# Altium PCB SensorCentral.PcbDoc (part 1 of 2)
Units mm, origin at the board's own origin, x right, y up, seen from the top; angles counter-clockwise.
Board outline 99.21 x 99.07 mm, 6 copper layers (Top Layer 1, GND1, Signal, GND2, GND3, Bottom Layer 1), stack 1.538 mm thick; 91 components, 67 nets, 452 pads, 462 vias.
Unrouted connection lines stored in the file: 278.
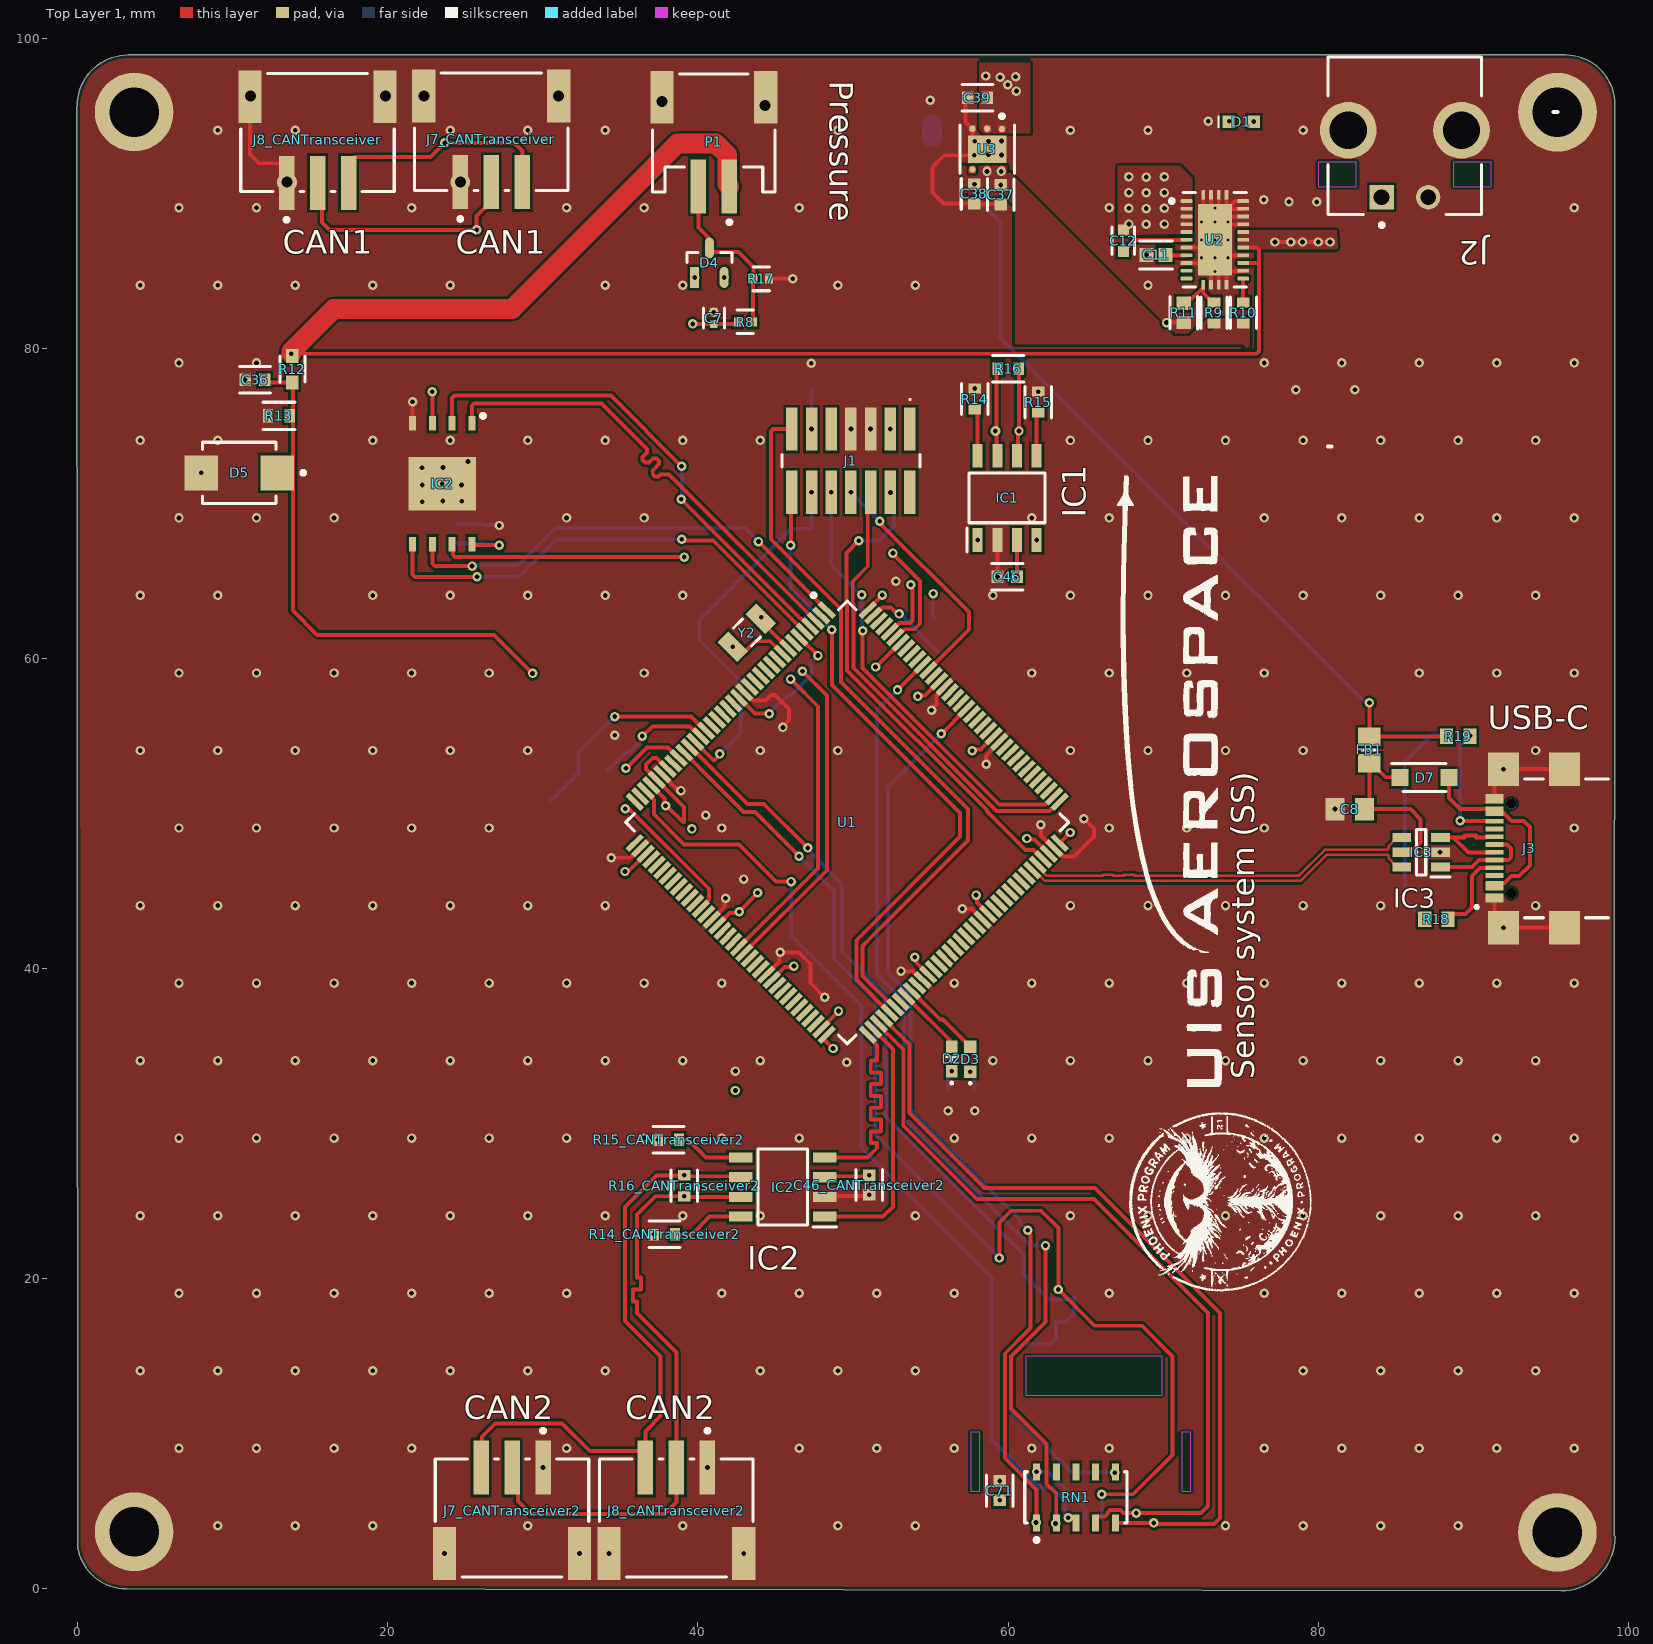
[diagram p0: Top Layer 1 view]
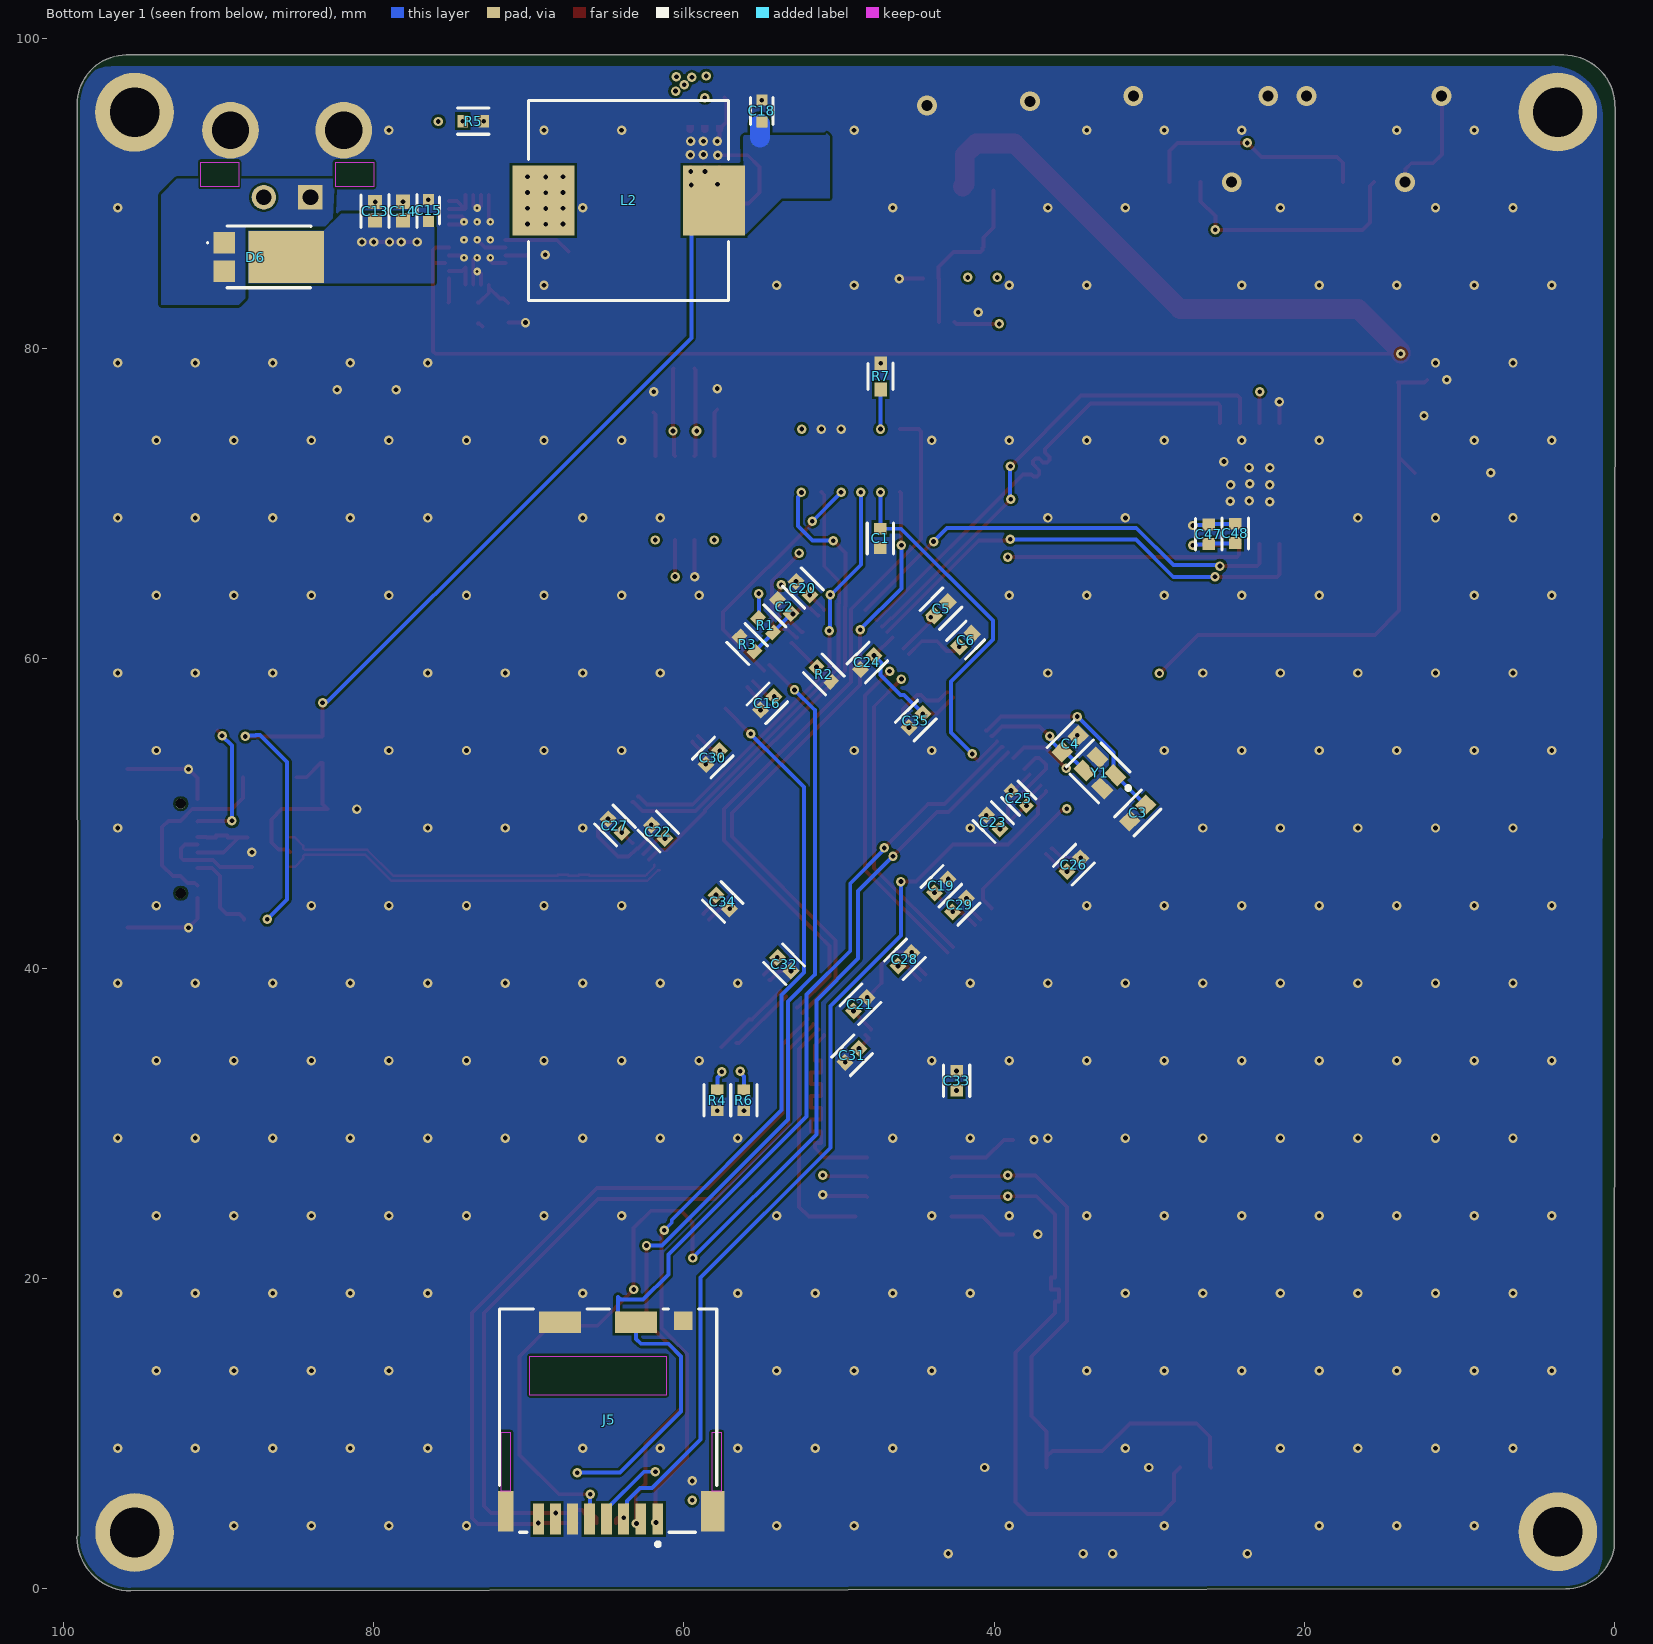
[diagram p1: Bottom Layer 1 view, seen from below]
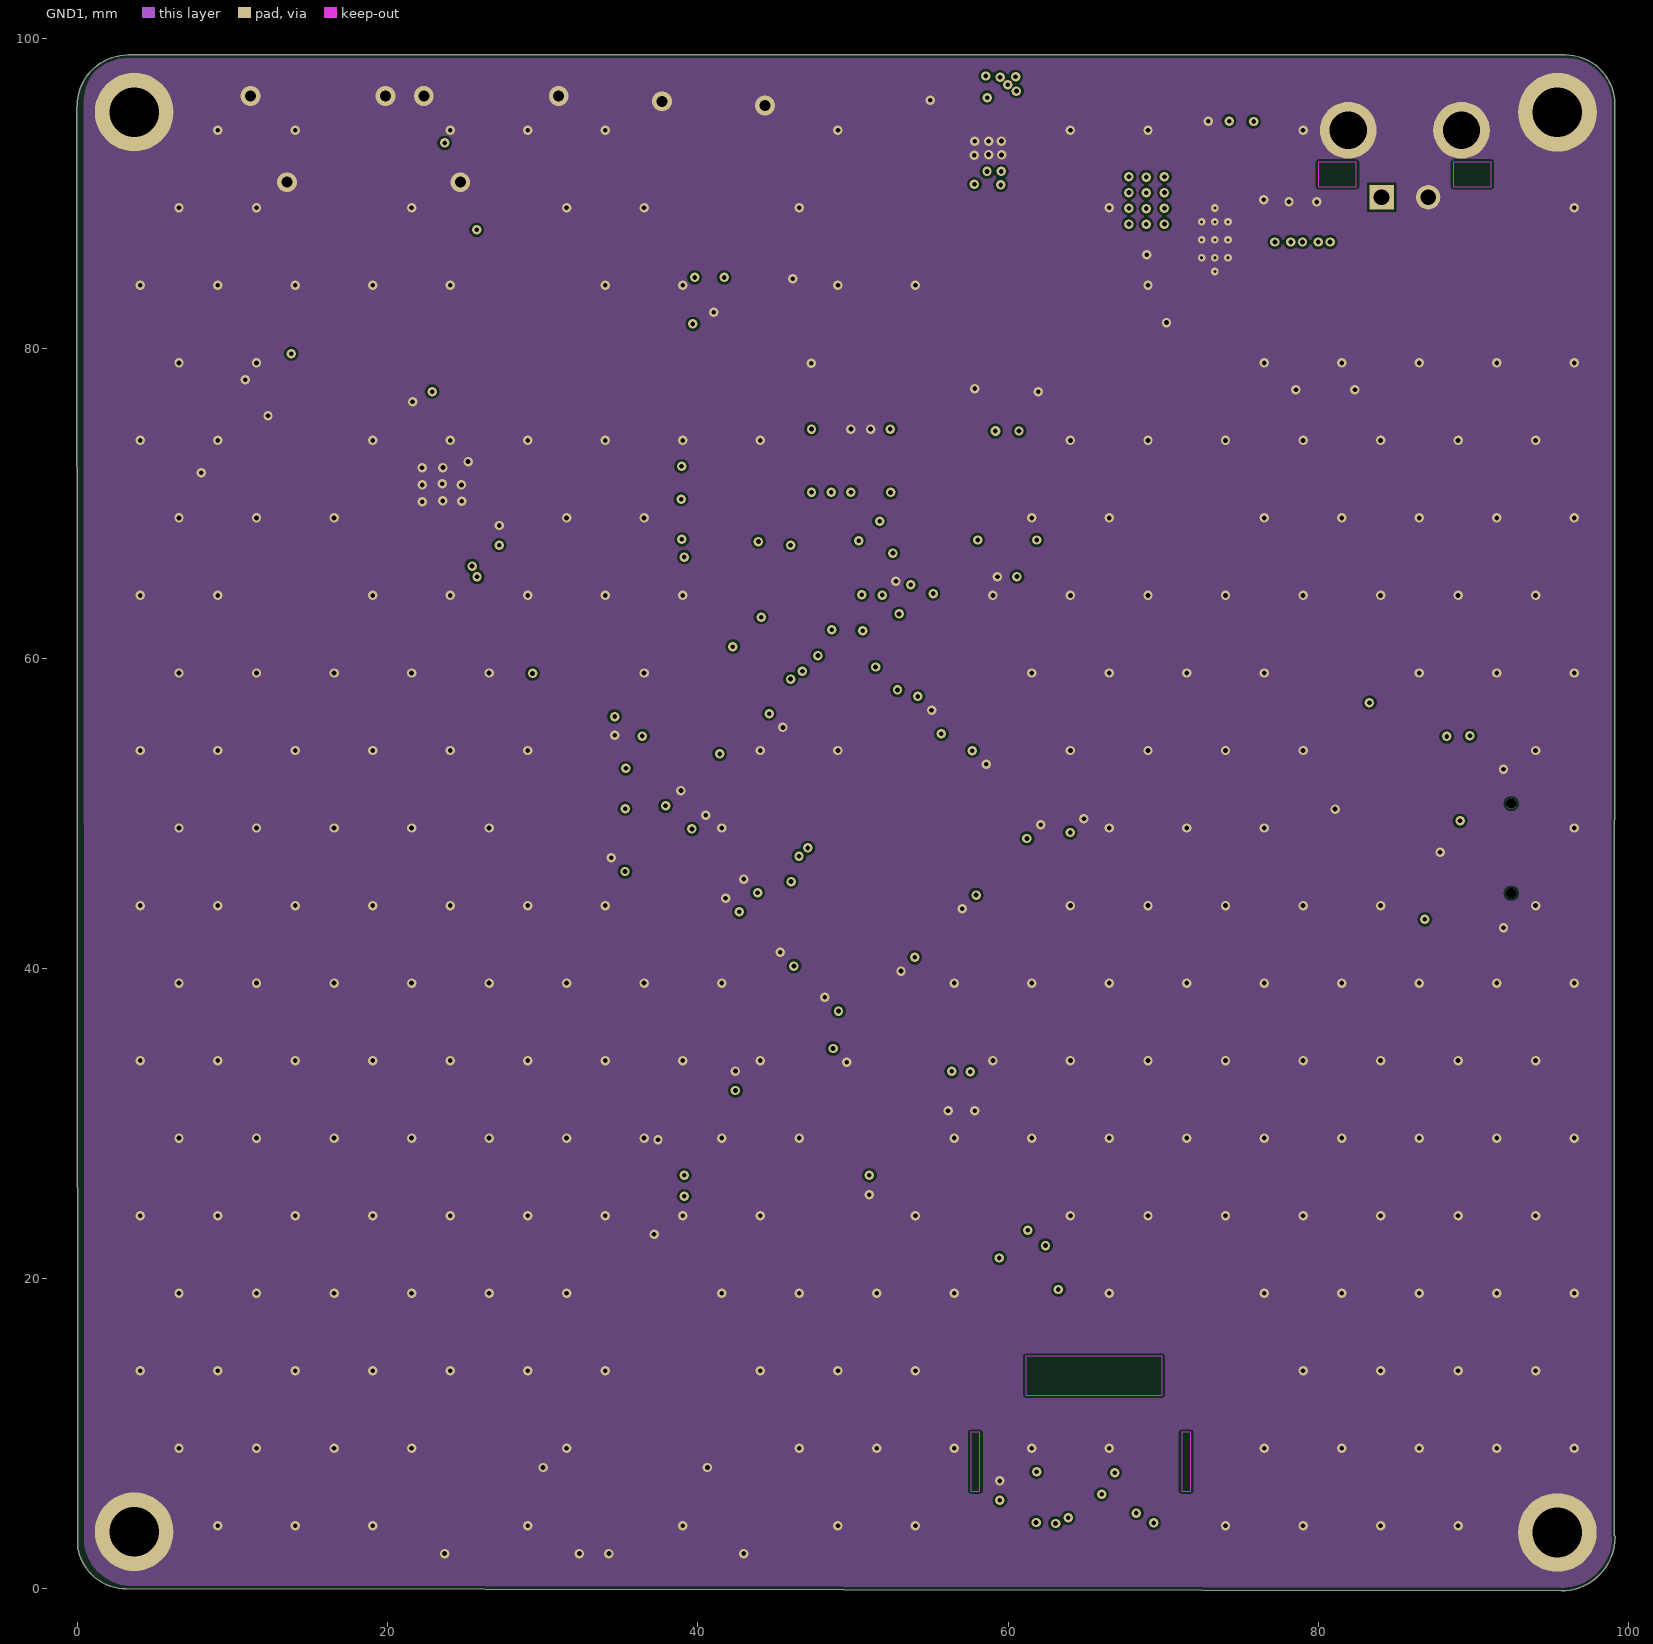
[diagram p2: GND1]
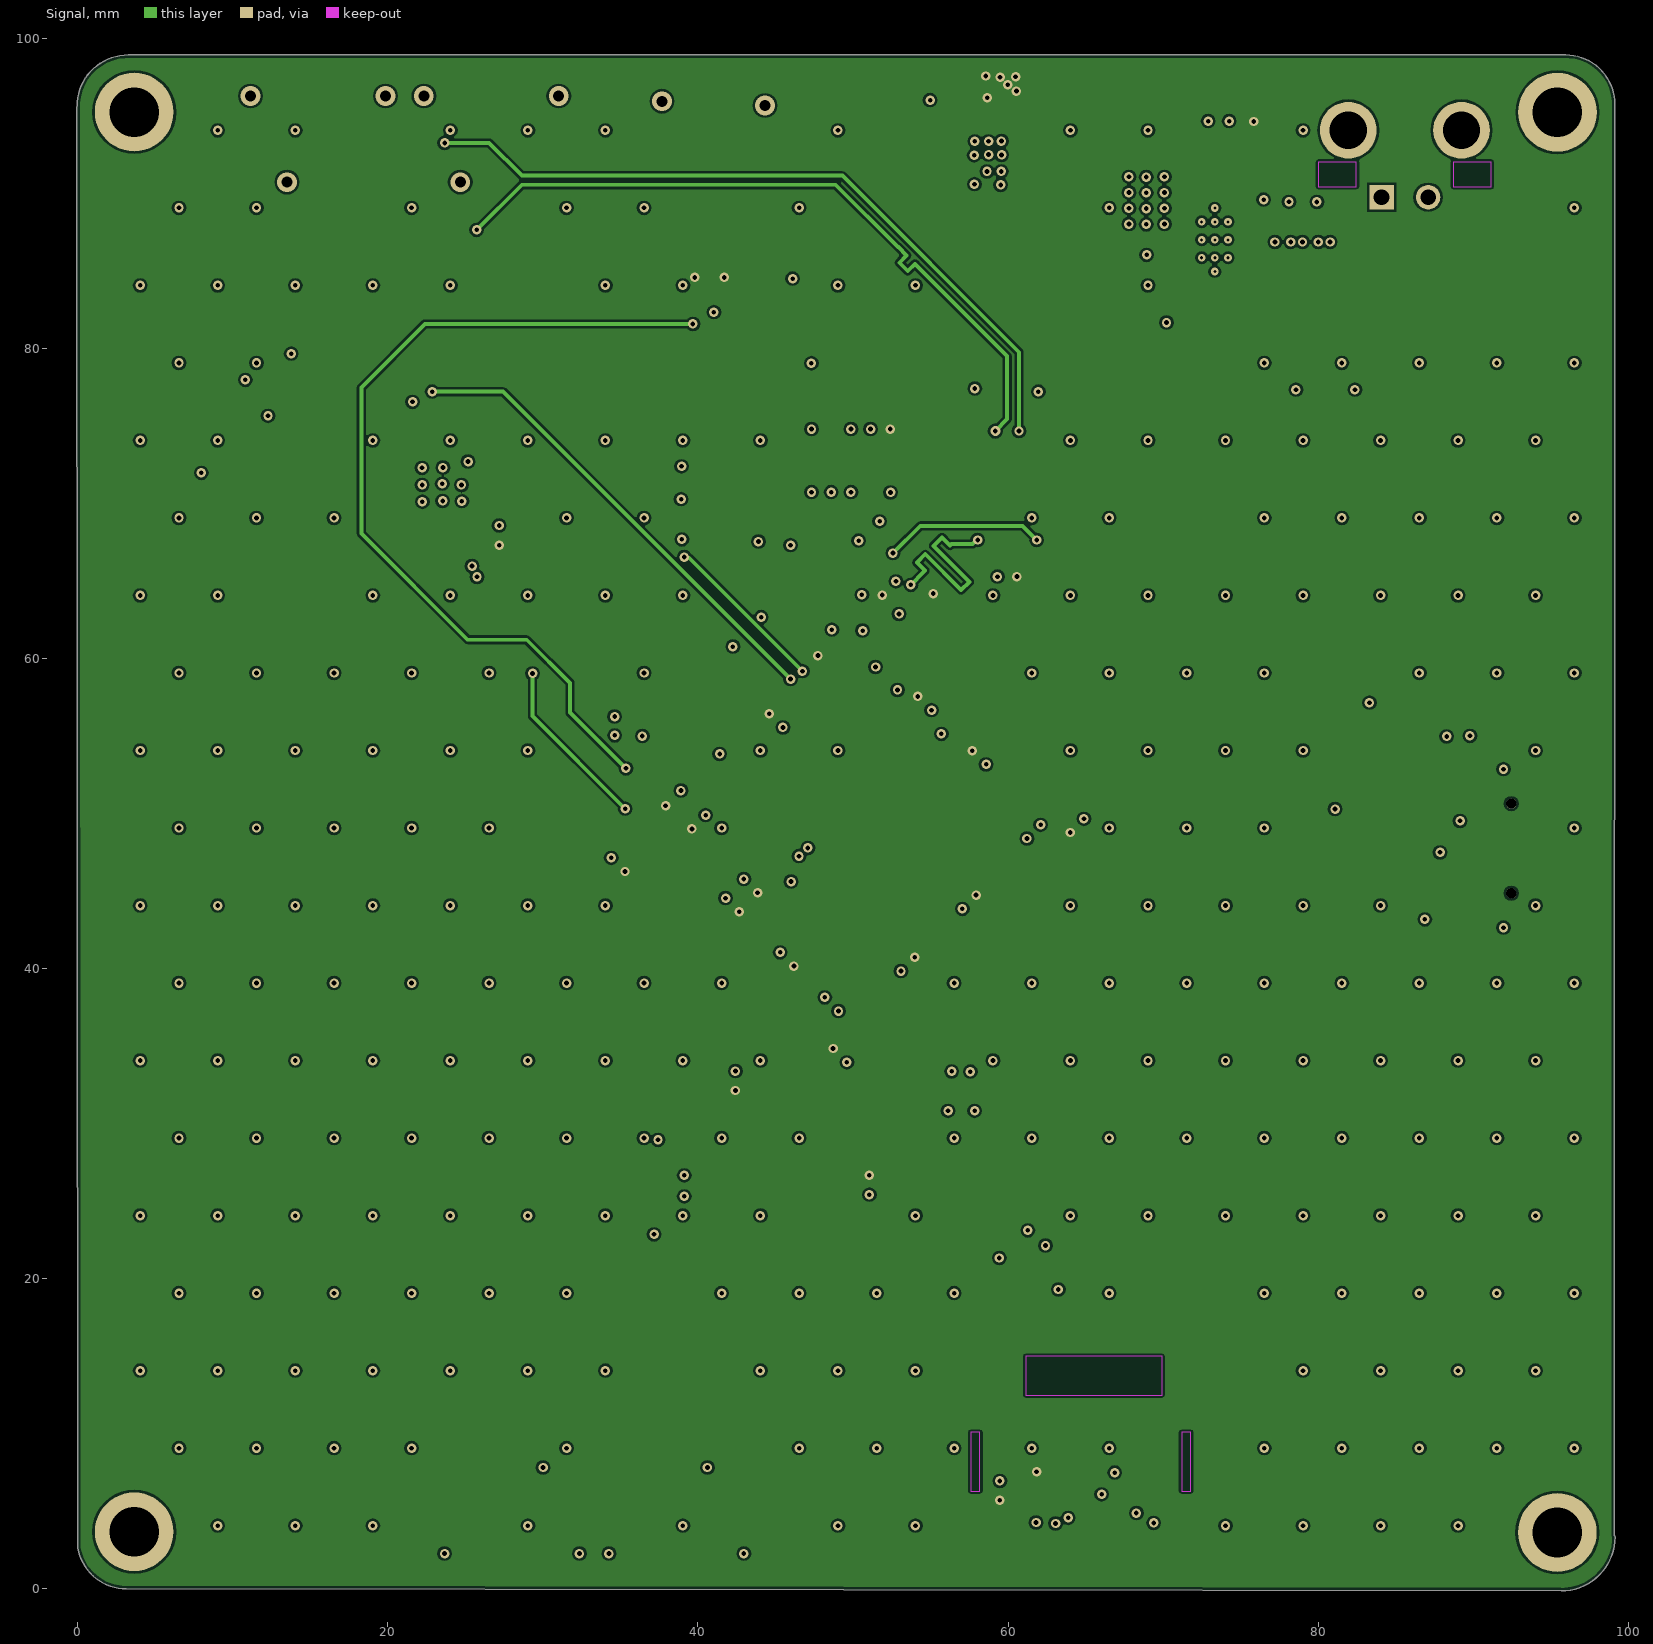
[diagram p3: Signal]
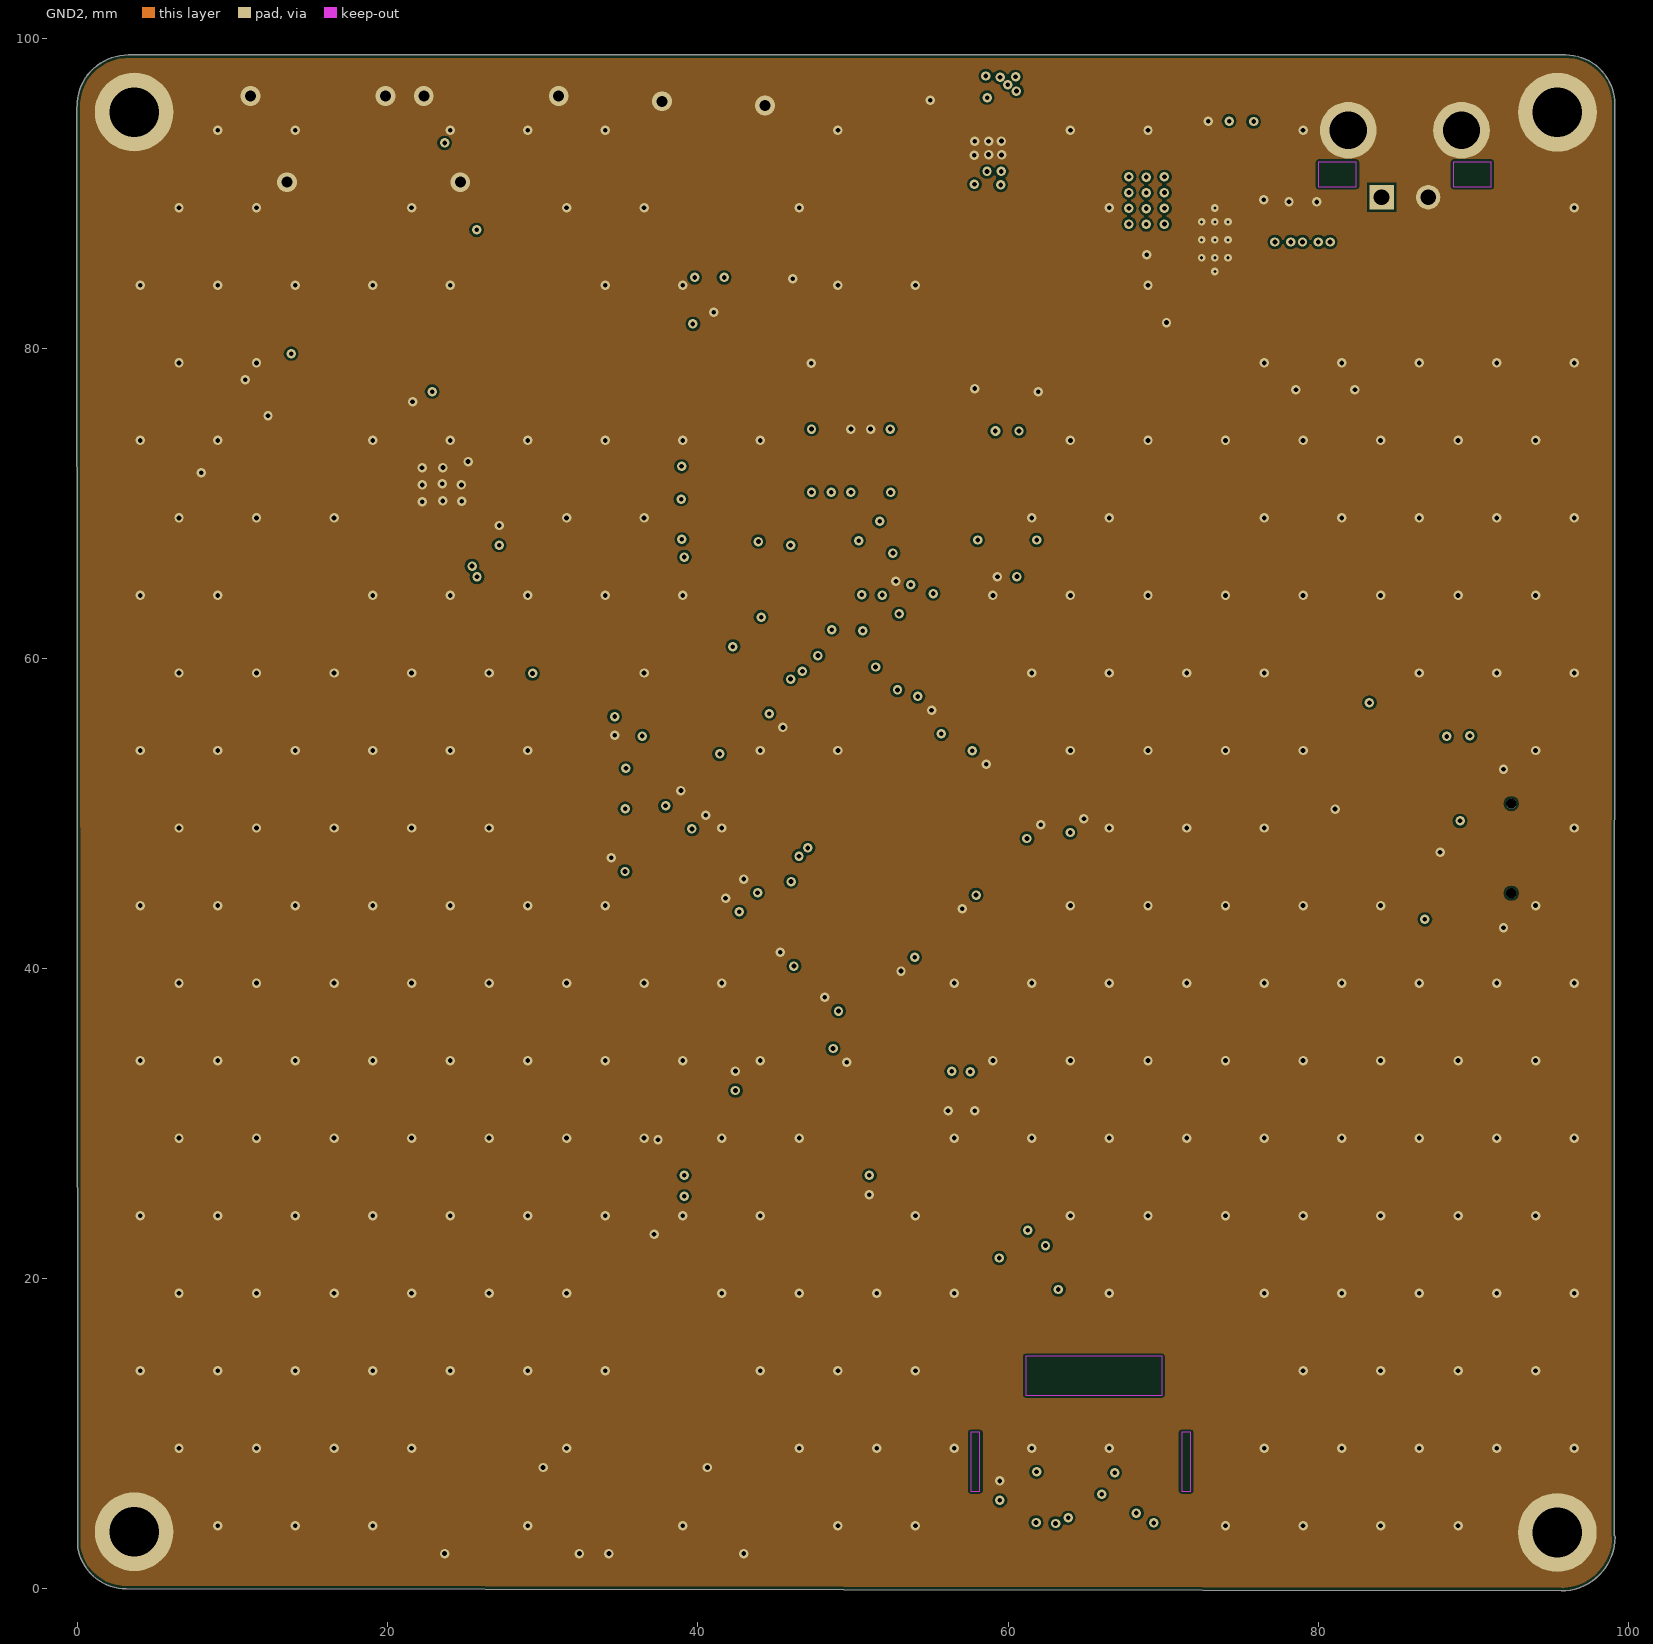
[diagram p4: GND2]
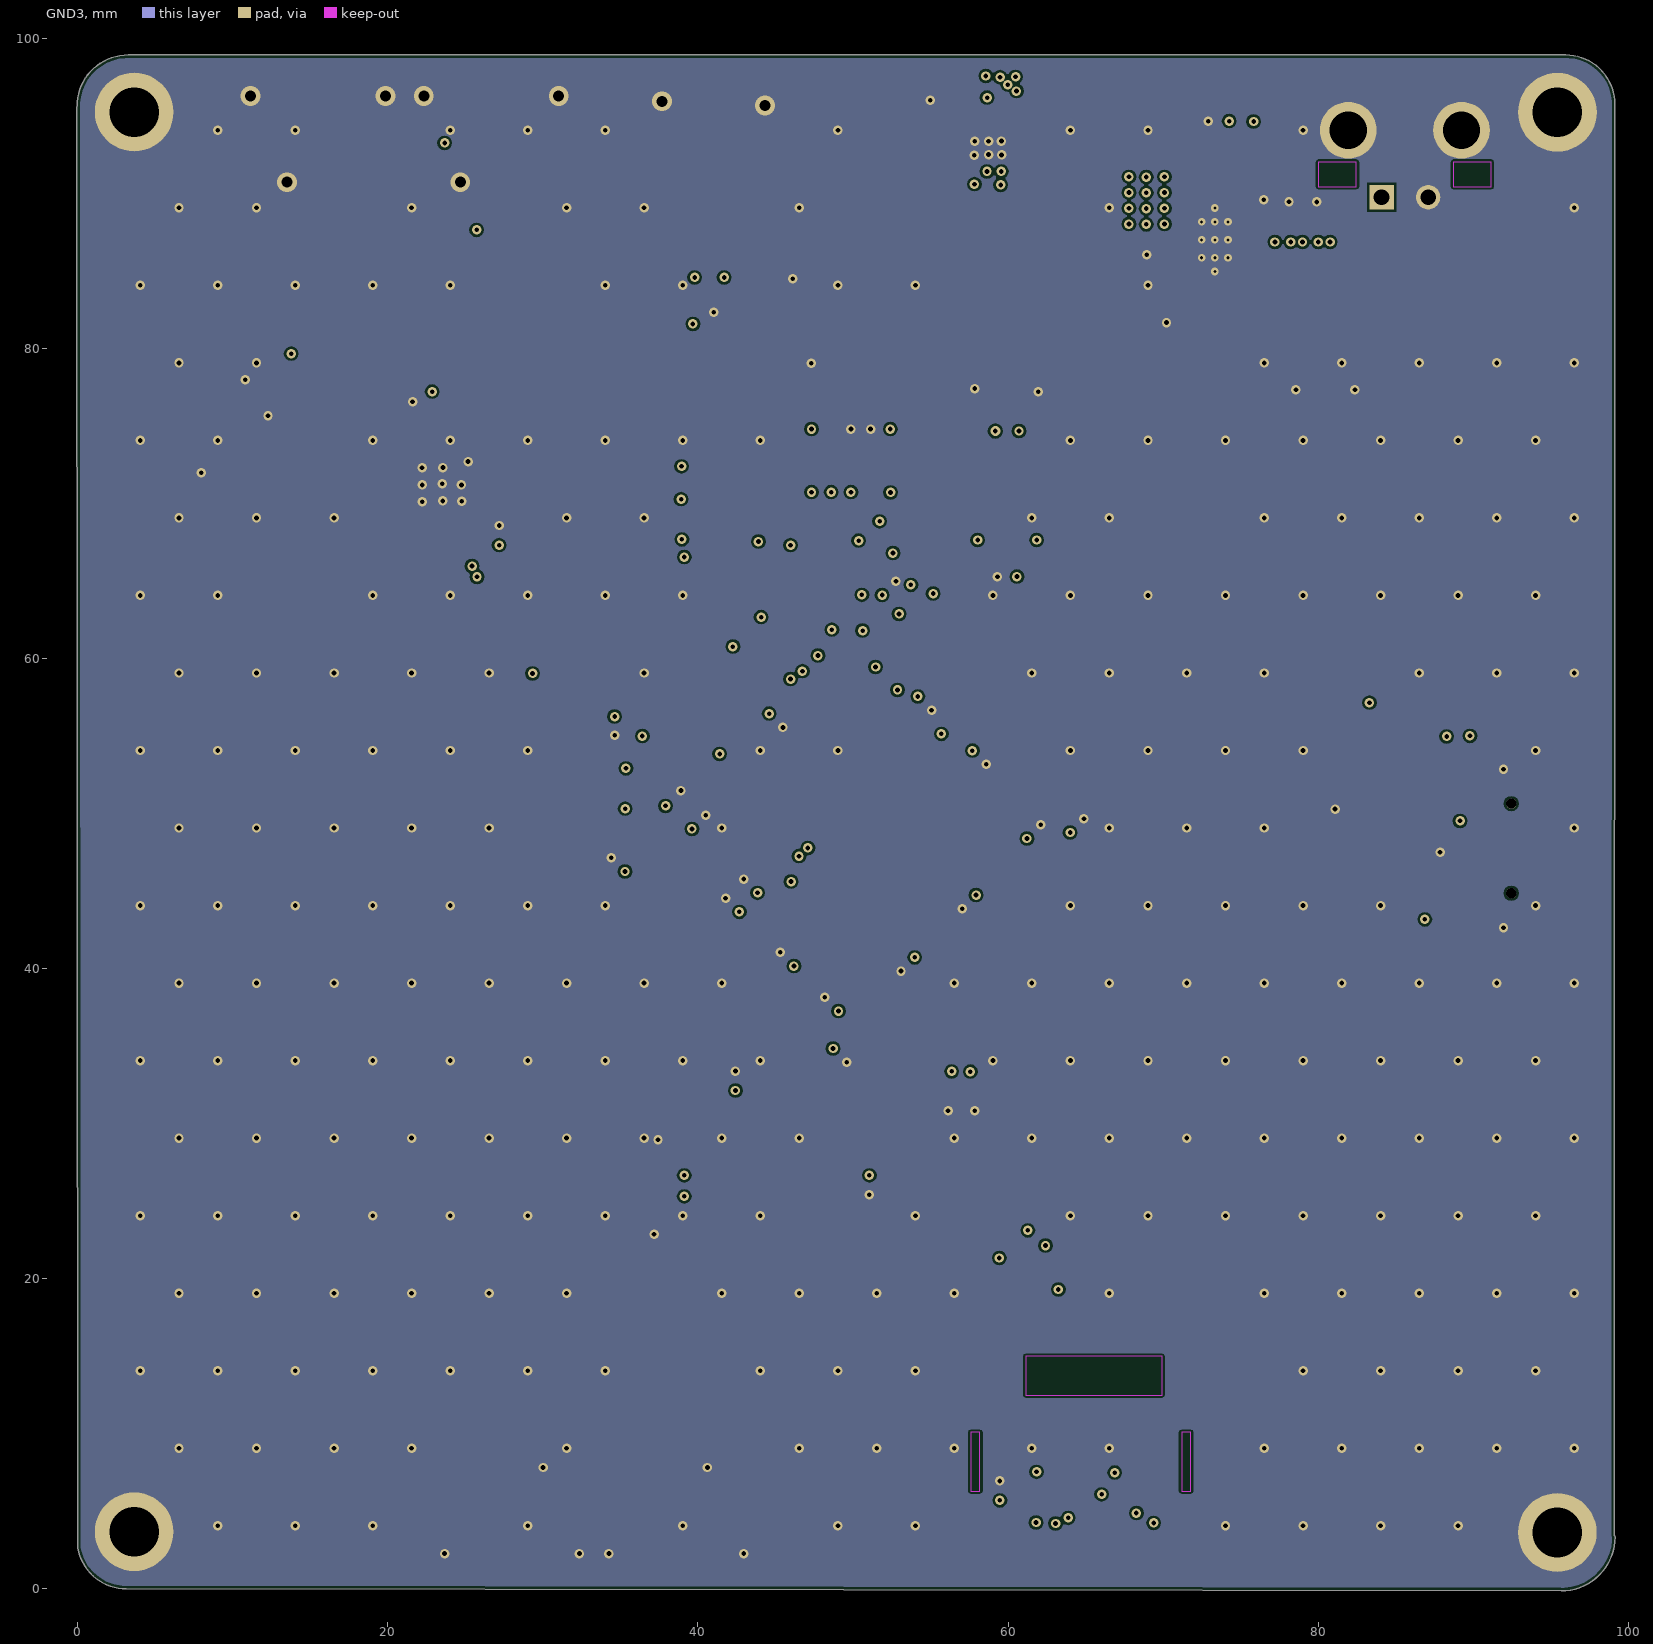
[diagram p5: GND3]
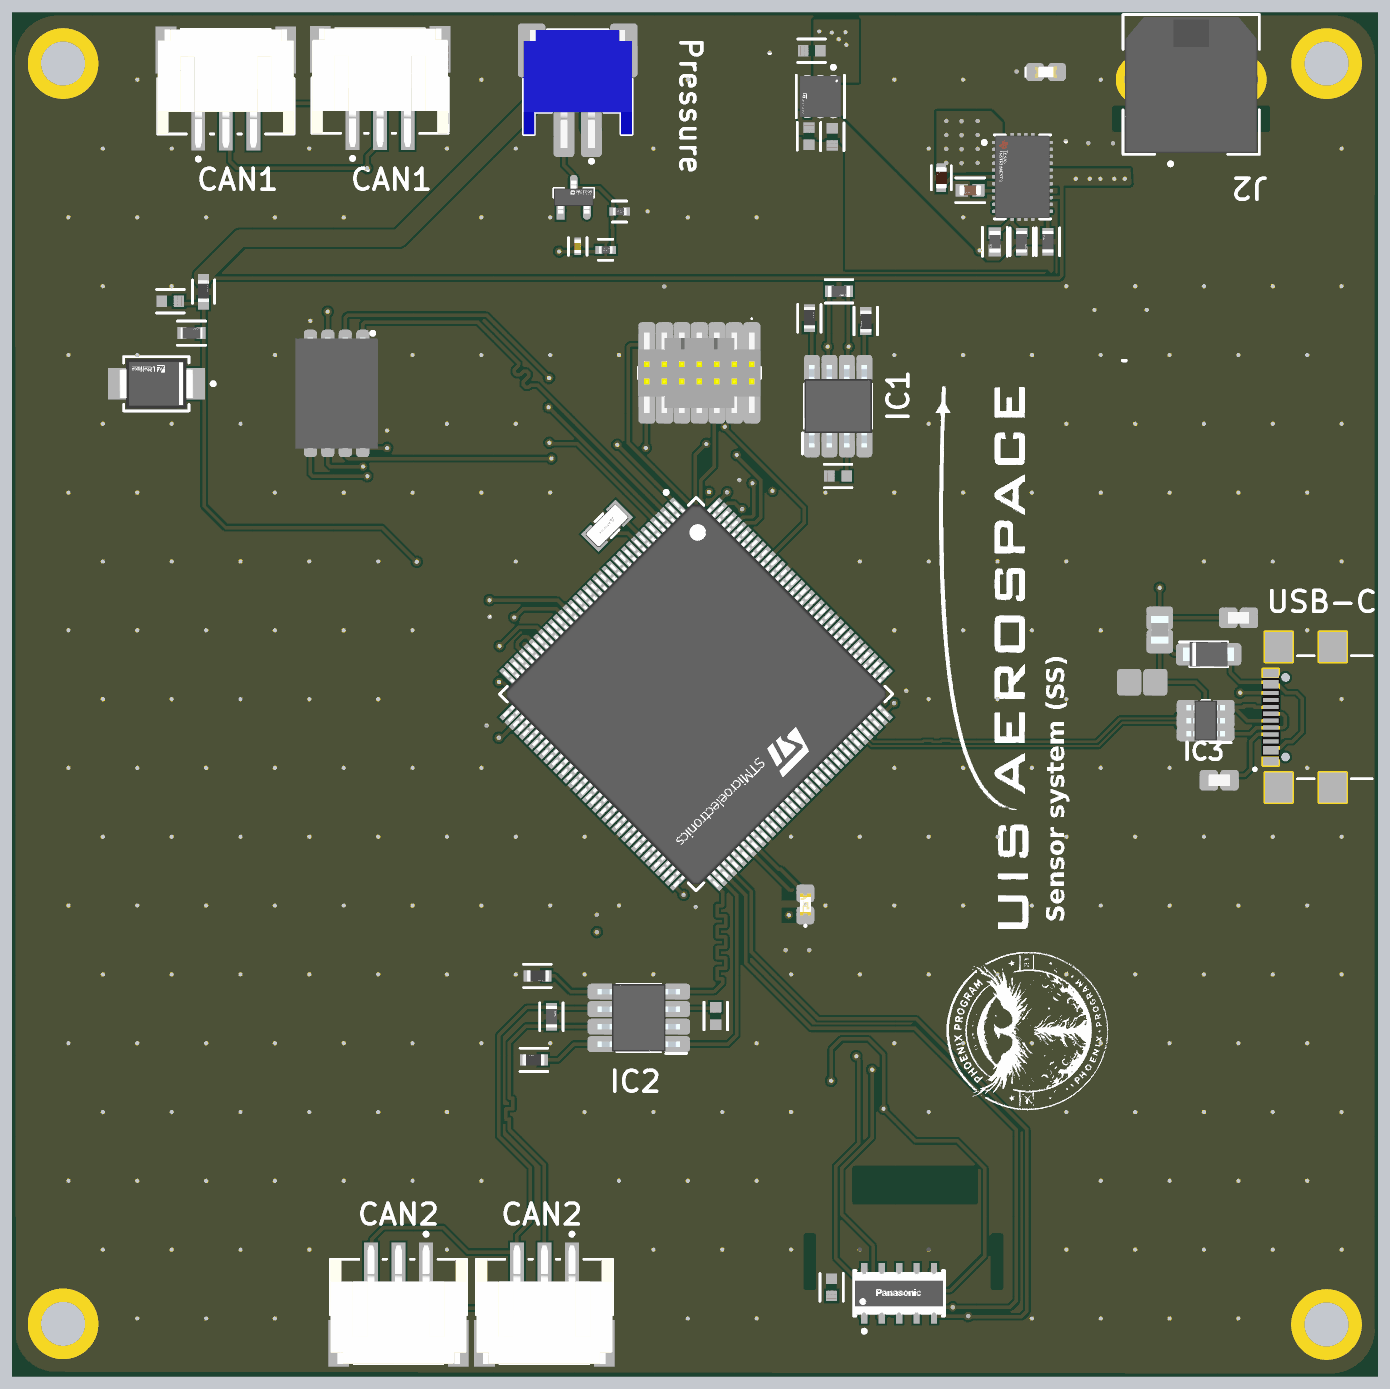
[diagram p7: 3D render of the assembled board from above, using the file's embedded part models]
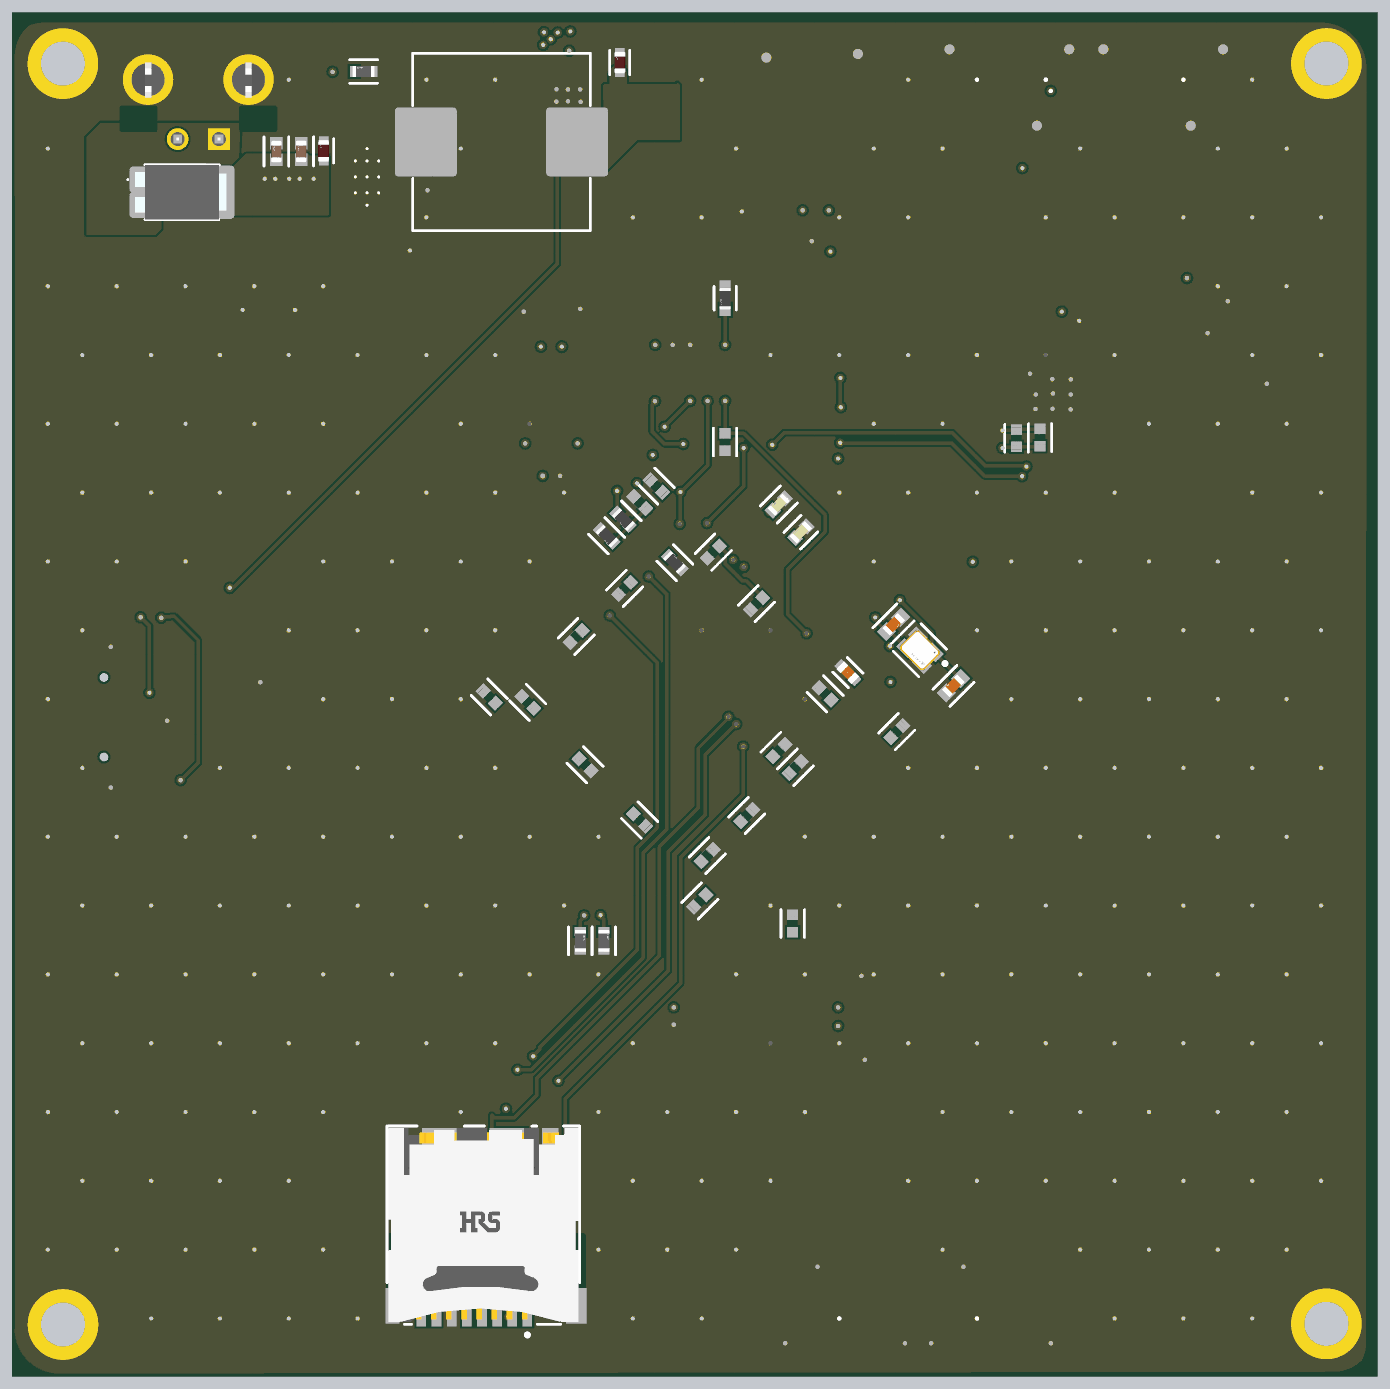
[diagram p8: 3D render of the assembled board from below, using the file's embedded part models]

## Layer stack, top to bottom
Top Solder: solder mask 0.0102, Solder Resist, Dk 3.5
Top Layer 1: signal copper 0.035
Dielectric 2: prepreg 0.0994, PP-006, Dk 4.1
GND1: signal copper 0.0152
Dielectric 4: core 0.55, PP-006, Dk 4.1
Signal: signal copper 0.0152
Dielectric 1: prepreg 0.1088, FR-4, Dk 4.8
GND2: signal copper 0.0152
Dielectric 5: core 0.55, PP-006, Dk 4.1
GND3: signal copper 0.0152
Dielectric 3: prepreg 0.0994, PP-006, Dk 4.1
Bottom Layer 1: signal copper 0.035
Bottom Solder: solder mask 0.0102, Solder Resist, Dk 3.5

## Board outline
-0.002,2.635 ccw(c3.128,3.171) 3.128,-0.004 95.673,-0.135 ccw(c95.673,3.344) 99.152,3.344 99.115,3.433 99.141,95.754 ccw(c95.965,95.754) 95.965,98.929 3.283,98.929 3.258,98.932 ccw(c3.258,95.627) -0.047,95.627 -0.055,95.576

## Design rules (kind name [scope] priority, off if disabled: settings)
BoardOutlineClearance [All] p1: gap=0.2 ignorepadtopadclearanceinfootprint=FALSE
Clearance "Stitching GND" [IsStitchingVia and InNet('GND') vs (IsVia and (Not IsStitchingVia)) Or IsPad] p1: gap=0.2 ignorepadtopadclearanceinfootprint=FALSE
Clearance [All] p2: gap=0.154 ignorepadtopadclearanceinfootprint=TRUE
ComponentClearance [All] p1: gap=0 collisioncheckmode=3 verticalgap=0 showdistances=FALSE
DiffPairsRouting [InDifferentialPair('OTG_FS')] p1: maxlimit=0.254 minlimit=0.127 mostfreqgap=0.254 toplayer_maxgap=0.127 toplayer_prefgap=0.127 toplayer_minwidth=0.165 toplayer_maxwidth=0.165 toplayer_prefwidth=0.165 bottomlayer_maxgap=0.127 bottomlayer_prefgap=0.127 bottomlayer_minwidth=0.165 bottomlayer_maxwidth=0.165 bottomlayer_prefwidth=0.165 impedanceprofiledriven=TRUE impedanceprofileid={DFCE3B1C-77C7-4DEB-9FE5-93ABBD900506} impedanceprofilevalue=90.000000 maxuncoupledlength=12.7
HoleSize [All] p1: absolutevalues=TRUE maxlimit=7.62 minlimit=0.2 maxpercent=80.000 minpercent=20.000
MatchedLengths DiffPair_MatchedLengths [InDifferentialPair ('RX')] p1: tolerance=25.4 checknetsindiffpair=FALSE checkdiffpairvsdiffpair=TRUE checkxsignals=TRUE checkothers=TRUE
MinimumAnnularRing [All] p1: minimumring=0.1
MinimumSolderMaskSliver [All] p1: minsoldermaskwidth=0.1
PasteMaskExpansion PasteMaskExpansion_1 [InPadClass('All Pads')] p1: expansion=0
PasteMaskExpansion [All] p2: expansion=0.254
PlaneClearance [All] p1: clearance=0.381
PlaneConnect [All] p1: pad.planeconnectstyle=Relief pad.reliefexpansion=0.508 pad.reliefentries=4 pad.reliefconductorwidth=0.254 pad.reliefairgap=0.254 via.planeconnectstyle=Direct via.reliefexpansion=0.508 via.reliefentries=4 via.reliefconductorwidth=0.254 via.reliefairgap=0.254
PolygonConnect [All] p1: connectstyle=Direct reliefconductorwidth=0.254 reliefentries=4 polygonreliefangle="90 Angle" airgapwidth=0.254
RoutingLayers [All] p1: top layer_v5=TRUE mid layer 1_v5=TRUE mid layer 2_v5=TRUE mid layer 3_v5=FALSE mid layer 4_v5=FALSE bottom layer_v5=TRUE
RoutingVias [All] p1: holewidth=0.305 width=0.61 viastyle="Through Hole" minholewidth=0.15 minwidth=0.25 maxholewidth=25.4 maxwidth=25.4
SMDNeckDown [All] p1 off: percent=100.000
SilkToSilkClearance [All] p1 off: silktosilkclearance=0.254
SilkToSolderMaskClearance SilkscreenOverComponentPads [IsPad] p1: minsilkscreentomaskgap=0.15 clearancetoexposedcopper=TRUE
SolderMaskExpansion [InPadClass('All Pads')] p1: expansion=0 istentingtop=FALSE useseparateexpansions=TRUE expansionbottom=0 istentingbottom=FALSE
SolderMaskExpansion SolderMaskExpansion_1 [All] p2: expansion=0.025 istentingtop=TRUE useseparateexpansions=TRUE expansionbottom=0.025 istentingbottom=TRUE
SupplyNets "Schematic Supply Nets_3" [InNet('VDD')] p1: voltage=0.000
SupplyNets "Schematic Supply Nets_4" [InNet('VBAT_IN')] p2: voltage=0.000
SupplyNets "Schematic Supply Nets_2" [InNet('VBAT')] p3: voltage=0.000
SupplyNets "Schematic Supply Nets_1" [InNet('GND')] p4: voltage=0.000
SupplyNets "Schematic Supply Nets" [InNet('DCREG5V0')] p5: voltage=0.000
Width [All] p1: maxlimit=12.7 minlimit=0.127 preferedwidth=0.254 midlayer1_maxwidth=1.27 midlayer2_maxwidth=1.27 midlayer3_maxwidth=1.27 midlayer4_maxwidth=1.27 minimp=50.000000 maximp=50.000000 favimp=50.000000
20 further rules are at their usual default settings.

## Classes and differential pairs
component class "USB C": C8 D7 FB1 IC3 J3 R18 R19
component class Pressure: C7 D4 R8 R17
channel class CANTransceiver: CANTransceiver CANTransceiver2
component class CANTransceiver2: C46_CANTransceiver2 IC2 J7_CANTransceiver2 J8_CANTransceiver2 R14_CANTransceiver2 R15_CANTransceiver2 R16_CANTransceiver2
component class TopLevel: J1 P1 R7
component class SD_CARD: C71 J5 RN1
component class Power: C11 C12 C13 C14 C15 C16 C18 C19 C20 C21 C22 C23 C24 C25 C26 C27 C28 C29 C30 C31 C32 C33 C34 C35 C36 C37 C38 C39 D5 D6 J2 L2 R9 R10 R11 R12 R13 U2 U3
component class MCU: C1 C2 C3 C4 C5 C6 D1 D2 D3 R1 R2 R3 R4 R5 R6 U1 Y1 Y2
component class CANTransceiver: C46 IC1 J7_CANTransceiver J8_CANTransceiver R14 R15 R16
component class 1GBIT_FLASH: C47 C48 IC2
differential pair OTG_FS: +OTG_FS_P -OTG_FS_N

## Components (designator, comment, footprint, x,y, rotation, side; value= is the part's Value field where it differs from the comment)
C1 "0.1uF" FP-CL10-IPC_C 47.33,67.747 r270 bottom
C2 "0.1uF" FP-CL10-IPC_C 53.526,63.354 r45 bottom
C3 "4pF" FP-GQM187-0_15-IPC_B 30.734,50.038 r315 bottom
C4 "4pF" FP-GQM187-0_15-IPC_B 35.088,54.499 r135 bottom
C5 "1.5pF" FP-C0603C-CF-IPC_C 43.419,63.209 r135 bottom value="1.5 pF"
C6 "1.5pF" FP-C0603C-CF-MFG 41.828,61.194 r135 bottom value="1.5 pF"
C7 "10 nF 402" FP-GJM155-0_05-IPC_C 41.027,81.96 r90 top
C8 "08053C104JAZ2A" CAPC2012X09N 82.042,50.292 r180 top value=100nF
C11 "2.2uF 50v" FP-GRM188-0_2-IPC_C 69.544,86.038 r180 top
C12 "0.47uF 50v" FP-0603-L_1_6_0_15-W_0_8-MFG 67.442,86.946 r90 top
C13 "2.2uF 50v" FP-GRM188-0_2-IPC_C 79.92,88.853 r90 bottom
C14 "2.2uF 50v" FP-GRM188-0_2-IPC_C 78.122,88.862 r90 bottom
C15 "0.47uF 50v" FP-0603-L_1_6_0_15-W_0_8-MFG 76.488,88.899 r90 bottom
C16 "0.1uF" FP-CL10-IPC_C 54.622,57.111 r315 bottom
C18 "0.47uF 50v" FP-0603-L_1_6_0_15-W_0_8-MFG 54.974,95.318 r90 bottom
C19 "10uF" FP-CL10-IPC_C 43.404,45.336 r135 bottom
C20 "0.1uF" FP-CL10-IPC_C 52.323,64.541 r45 bottom
C21 "2.2uF" FP-CL10-IPC_C 48.622,37.705 r135 bottom
C22 "2.2uF" FP-CL10-IPC_C 61.659,48.835 r45 bottom
C23 "1uF" FP-CL10-IPC_C 40.053,49.451 r45 bottom
C24 "0.1uF" FP-CL10-IPC_C 48.179,59.747 r315 bottom
C25 "4.7uF" FP-C1608-080-0_1-MFG 38.405,50.992 r225 bottom
C26 "0.1uF" FP-CL10-IPC_C 34.851,46.707 r135 bottom
C27 "0.1uF" FP-CL10-IPC_C 64.452,49.222 r45 bottom
C28 "0.1uF" FP-CL10-IPC_C 45.748,40.607 r135 bottom
C29 "0.1uF" FP-CL10-IPC_C 42.224,44.105 r135 bottom
C30 "0.1uF" FP-CL10-IPC_C 58.143,53.617 r315 bottom
C31 "0.1uF" FP-CL10-IPC_C 49.157,34.404 r315 bottom
C32 "0.1uF" FP-CL10-IPC_C 53.539,40.285 r225 bottom
C33 "0.1uF" FP-CL10-IPC_C 42.418,32.766 r90 bottom
C34 "0.1uF" FP-CL10-IPC_C 57.495,44.301 r225 bottom
C35 "0.1uF" FP-CL10-IPC_C 45.038,56.003 r315 bottom
C36 "0.1uF" FP-CL10-IPC_C 11.43,77.978 r180 top
C37 "10uF" FP-CL10-IPC_C 59.522,89.919 r270 top
C38 "0.1uF" FP-CL10-IPC_C 57.833,89.966 r270 top
C39 "10uF" FP-CL10-IPC_C 58.024,96.176 r180 top
C46 "1uF" FP-CL10-IPC_C 59.944,65.278 r180 top
C46_CANTransceiver2 "1uF" FP-CL10-IPC_C 51.054,26.043 r270 top (schematic designator C46)
C47 "0.1uF" FP-CL10-IPC_C 26.151,68.022 r90 bottom
C48 "1uF" FP-CL10-IPC_C 24.444,68.072 r90 bottom
C71 "0.1uF" FP-CL10-IPC_C 59.473,6.331 r90 top
D1 "150060RS75000" WL-SMCW_0603_150060xx75000 75.045,94.628 r0 top
D2 "150060GS55040" WL-SMCD_0603 -1213.633,1304.173 r90 top
D3 "150060YS75020" WL-SMCW_0603_150060xx75020 57.566,34.153 r90 top
D4 "BAT54A" FP-BAT54A-IPC_B 40.738,85.533 r90 top
D5 "SMBJ33A" FP-SMBJ-MFG 10.414,71.98 r180 top
D6 "SBRT10U50SP5-13" SBRT10U50SP513 86.873,85.897 r270 bottom
D7 "SS34LWHRVG" SODFL3718X102N 86.868,52.324 r0 top
FB1 "MPZ2012S101AT000" BEADC2012X105N 83.312,54.102 r270 top
IC1 "TCAN3414DR" SOIC127P600X175-8N 59.944,70.358 r90 top
IC2 "TCAN3414DR" SOIC127P600X175-8N 45.466,25.908 r180 top (schematic designator IC1)
IC2 "W25Q01JVZEIM_TU" SON127P800X600X80-9N-D 23.507,71.276 r270 top locked
IC3 "USBLC6-2SC6" SOT95P280X145-6N 86.645,47.508 r180 top
J1 "FTSH-107-01-L-DV-K-TR" FTSH10701LDVKTR 49.864,72.767 r180 top locked
J2 "43650-0205" FP-43650-0205-MFG 85.598,93.726 r180 top
J3 "USB4940-00-A_REVA" GCT_USB4940-00-A_REVA 92.456,47.752 r90 top
J5 "DM3CS-SF" FP-DM3CS-SF-MFG 64.888,10.849 r180 bottom
J7_CANTransceiver "S3B-PH-SM4-TB(LF)(SN)" FP-S3B-PH-SM4-TB_LF_SN-MFG 26.67,93.98 r0 top (schematic designator J7)
J7_CANTransceiver2 "S3B-PH-SM4-TB(LF)(SN)" FP-S3B-PH-SM4-TB_LF_SN-MFG 28.008,4.572 r180 top (schematic designator J7)
J8_CANTransceiver "S3B-PH-SM4-TB(LF)(SN)" FP-S3B-PH-SM4-TB_LF_SN-MFG 15.462,93.928 r0 top (schematic designator J8)
J8_CANTransceiver2 "S3B-PH-SM4-TB(LF)(SN)" FP-S3B-PH-SM4-TB_LF_SN-MFG 38.608,4.572 r180 top (schematic designator J8)
L2 "SRP1270-100M" BOUR-SRP1270-100M-2_V 63.569,89.549 r180 bottom
P1 "S2B-PH-SM4-TB(LF)(SN)" "JST- S2B-PH-SM4-TB(LF)(SN)-2_V" 41.027,93.898 r180 top
R1 "10k" FP-RT0603-IPC_C 54.742,62.146 r225 bottom value=10KΩ
R2 "10k" FP-RT0603-IPC_C 50.977,58.978 r45 bottom value=10KΩ
R3 "10k" FP-RT0603-IPC_C 55.928,60.934 r225 bottom value=10KΩ
R4 "220 0603" FP-AF0603-IPC_C 57.847,31.507 r90 bottom
R5 "220 0603" FP-AF0603-IPC_C 73.588,94.664 r0 bottom
R6 "220 0603" FP-AF0603-IPC_C 56.134,31.507 r90 bottom
R7 "100" FP-RT0603-MFG 47.315,78.197 r270 bottom value=100Ω
R8 "10 K" FP-RP73P-1E-MFG 43.059,81.706 r180 top value=165Ω
R9 "100k" FP-RC0603-0_55-IPC_C 73.284,82.296 r270 top
R10 "100k" FP-RC0603-0_55-IPC_C 75.184,82.296 r90 top
R11 "24.9k" FP-RG1608-IPC_C 71.334,82.296 r270 top
R12 "147K" FP-RT0603-MFG 13.837,78.669 r90 top value=147KΩ
R13 "10K" FP-ERJPB3-IPC_C 12.969,75.659 r0 top
R14 "10k" FP-RT0603-IPC_C 57.855,76.737 r90 top value=10KΩ
R14_CANTransceiver2 "10k" FP-RT0603-IPC_C 37.846,22.86 r180 top value=10KΩ (schematic designator R14)
R15 "10k" FP-RT0603-IPC_C 61.954,76.539 r270 top value=10KΩ
R15_CANTransceiver2 "10k" FP-RT0603-IPC_C 38.1,28.956 r0 top value=10KΩ (schematic designator R15)
R16 "120" FP-AF0603-IPC_C 60.011,78.695 r0 top
R16_CANTransceiver2 "120" FP-AF0603-IPC_C 39.116,25.993 r90 top (schematic designator R16)
R17 "165" FP-RP73P-1E-MFG 44.075,84.5 r0 top value=165Ω
R18 "56k" RESC1608X50N 87.63,43.18 r0 top
R19 "56k" RESC1608X50N 89.039,54.977 r180 top
RN1 "EXB-A10P103J" FP-EXBA-MFG 64.38,5.897 r0 top
U1 "STM32H753ZIT6" FP-LQFP144-1A-MFG 49.628,49.431 r315 top locked
U2 "LM76005RNPR" FP-RNP0030A-MFG 73.34,87.009 r0 top
U3 "LD39200PU33R" FP-DFN6-7946637-MFG 58.655,92.851 r270 top
Y1 "ABM10W-50.0000MHZ-4-B1U-T3" FP-ABM10W-MFG 33.171,52.623 r45 bottom
Y2 "ABS07AIG-32.768KHZ-6-D-T" FP-ABS07AIG-MFG 43.154,61.671 r225 top

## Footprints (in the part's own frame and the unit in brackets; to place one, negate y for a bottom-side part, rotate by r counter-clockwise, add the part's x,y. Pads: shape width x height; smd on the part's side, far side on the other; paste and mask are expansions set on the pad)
BEADC2012X105N [mm]
  rect 1.2x1.45 smd: 1(-0.85,0) 2(0.85,0)
  silkscreen extent 0,-0.53 0,0.53, body extent -1,-0.63 1,0.63, height 1.05
BOUR-SRP1270-100M-2_V [mm] "SMD, 2-Leads, Body 12.9x12.9mm"
  rect 4x4.5 smd: 1(-5.5,0) 2(5.5,0)
  silkscreen extent -6.45,-6.45 6.45,6.45, body extent -6.45,-6.45 6.45,6.45, height 7
CAPC2012X09N [mm] "Chip Capacitor, 2-Leads, Body 2,05x1,25mm, IPC Medium Density"
  rect 1.25x1.45 smd: 1(-0.95,0) 2(0.95,0)
  body extent -1.08,-0.72 1.07,0.72, height 0.94
FP-0603-L_1_6_0_15-W_0_8-MFG [mm]
  rect 0.7x0.7 smd paste+0 mask+0: 1(-0.7,0) 2(0.7,0)
  silkscreen extent -0.87,-0.72 0.87,0.72, body extent -0.8,-0.4 0.8,0.4, height 0.95
FP-43650-0205-MFG [mm]
  rect 1.57x1.57 hole 1.02 paste-2539.97 mask+0: 1(1.5,3.97)
  round 1.57 hole 1.02 paste-2539.97 mask+0: 2(-1.5,3.97)
  round 3.66 hole 2.41 paste-2539.97 mask+0: 3(-3.65,-0.35) 4(3.65,-0.35)
  Keep-Out Layer region: -5.575,1.7 -3.125,1.7 -3.125,3.3 -5.575,3.3
  Keep-Out Layer region: 3.125,1.7 5.575,1.7 5.575,3.3 3.125,3.3
  silkscreen extent -4.95,-5.07 4.95,5.89, body extent -5.58,-5.18 5.58,5.18, height 0.25
FP-ABM10W-MFG [mm]
  rect 1.2x0.85 smd paste+0 mask+0: 1(-0.812,-0.6) 2(0.812,-0.6) 3(0.812,0.6) 4(-0.812,0.6)
  silkscreen extent -2.1,-1.42 1.3,1.43, body extent -1.25,-1 1.25,1, height 0.6
FP-ABS07AIG-MFG [mm]
  rect 1x1.8 smd paste+0 mask+0: 1(-1.275,0) 2(1.275,0)
  silkscreen extent -0.4,-0.82 0.4,0.82, body extent -1.6,-0.75 1.6,0.75, height 0.9
FP-AF0603-IPC_C [mm]
  rect 0.659x0.812 smd paste+0 mask+0: 1(-0.677,0) 2(0.677,0)
  silkscreen extent -1.01,-0.85 1.01,0.85, body extent -0.8,-0.4 0.8,0.4, height 0.55
FP-BAT54A-IPC_B [mm]
  rect 1.357x0.572 smd paste+0 mask+0: 1(-0.951,0.95)
  rrect100% 1.357x0.572 smd paste+0 mask+0: 2(-0.951,-0.95) 3(0.951,0)
  silkscreen extent 0,-1.45 0.65,1.45, body extent -1.88,-1.7 1.88,1.7, height 0.25
FP-C0603C-CF-IPC_C [mm]
  rect 0.807x0.858 smd paste+0 mask+0: 1(-0.626,0) 2(0.626,0)
  silkscreen extent -1.03,-0.88 1.03,0.88, body extent -0.8,-0.4 0.8,0.4, height 0.87
FP-C0603C-CF-MFG [mm]
  rect 0.75x0.9 smd paste+0 mask+0: 1(-0.6,0) 2(0.6,0)
  silkscreen extent -0.87,-0.85 0.88,0.85, body extent -0.8,-0.4 0.8,0.4, height 0.87
FP-C1608-080-0_1-MFG [mm]
  rect 0.7x0.7 smd paste+0 mask+0: 1(-0.7,0) 2(0.7,0)
  silkscreen extent -0.8,-0.75 0.8,0.75, body extent -0.8,-0.4 0.8,0.4, height 0.9
FP-CL10-IPC_C [mm]
  rect 0.758x0.812 smd paste+0 mask+0: 1(-0.627,0) 2(0.627,0)
  silkscreen extent -1.01,-0.85 1.01,0.85, body extent -0.8,-0.4 0.8,0.4, height 0.9
FP-DFN6-7946637-MFG [mm]
  round 0.405 smd paste+0 mask+0: 1(-1.3,0.95) 2(-1.321,0) 3(-1.321,-0.95) 4(1.3,-0.95) 5(1.321,0) 6(1.321,0.95)
  rect 1.75x2.5 smd paste+0 mask+0: 7(0,0)
  Top Layer 1 region: -1.55,1.175 -1.275,1.175 -1.189,1.158 -1.116,1.109 -1.067,1.036 -1.05,0.95 -1.05,0.95 -1.067,0.864 -1.116,0.791 -1.189,0.742 -1.275,0.725 -1.275,0.725 -1.55,0.725
  Top Layer 1 region: -1.55,0.225 -1.275,0.225 -1.189,0.208 -1.116,0.159 -1.067,0.086 -1.05,0 -1.05,0 -1.067,-0.086 -1.116,-0.159 -1.189,-0.208 -1.275,-0.225 -1.275,-0.225 -1.55,-0.225
  Top Layer 1 region: -1.55,-0.725 -1.275,-0.725 -1.189,-0.742 -1.116,-0.791 -1.067,-0.864 -1.05,-0.95 -1.05,-0.95 -1.067,-1.036 -1.116,-1.109 -1.189,-1.158 -1.275,-1.175 -1.275,-1.175 -1.55,-1.175
  Top Layer 1 region: 1.55,0.725 1.275,0.725 1.189,0.742 1.116,0.791 1.067,0.864 1.05,0.95 1.05,0.95 1.067,1.036 1.116,1.109 1.189,1.158 1.275,1.175 1.275,1.175 1.55,1.175
  Top Layer 1 region: 1.55,-0.225 1.275,-0.225 1.189,-0.208 1.116,-0.159 1.067,-0.086 1.05,0 1.05,0 1.067,0.086 1.116,0.159 1.189,0.208 1.275,0.225 1.275,0.225 1.55,0.225
  Top Layer 1 region: 1.55,-1.175 1.275,-1.175 1.189,-1.158 1.116,-1.109 1.067,-1.036 1.05,-0.95 1.05,-0.95 1.067,-0.864 1.116,-0.791 1.189,-0.742 1.275,-0.725 1.275,-0.725 1.55,-0.725
  silkscreen extent -2.25,-1.75 1.55,1.75, body extent -1.65,-1.65 1.65,1.65, height 0.25
FP-DM3CS-SF-MFG [mm]
  rect 0.7x2 smd paste+0 mask+0: 1(3.2,-6.35) 2(2.1,-6.35) 3(1,-6.35) 4(-0.1,-6.35) 5(-1.2,-6.35) 6(-2.3,-6.35) 7(-3.4,-6.35) 8(-4.5,-6.35)
  rect 2.7x1.4 smd paste+0 mask+0: 9(-3.1,6.35) 10(1.8,6.35)
  rect 1.2x1.2 smd paste+0 mask+0: 11(4.85,6.45)
  rect 1x2.6 smd paste+0 mask+0: 12(-6.6,-5.85)
  rect 1.5x2.6 smd paste+0 mask+0: 13(6.75,-5.85)
  Keep-Out Layer region: -5.05,4.15 3.75,4.15 3.75,1.65 -5.05,1.65
  Keep-Out Layer region: 6.7,-0.75 7.3,-0.75 7.3,-4.55 6.7,-4.55
  Keep-Out Layer region: -6.9,-0.75 -6.3,-0.75 -6.3,-4.55 -6.9,-4.55
  silkscreen extent -7,-8.1 7,7.2, body extent -6.9,-7.05 6.9,7.05, height 2.13
FP-ERJPB3-IPC_C [mm]
  rect 0.657x0.862 smd paste+0 mask+0: 1(-0.701,0) 2(0.701,0)
  silkscreen extent -1.03,-0.87 1.03,0.87, body extent -0.8,-0.4 0.8,0.4, height 0.55
FP-EXBA-MFG [mm]
  rect 0.45x1.1 smd paste+0 mask+0: 1(-2.54,-1.65) 2(-1.27,-1.65) 3(0,-1.65) 4(1.27,-1.65) 5(2.54,-1.65) 6(2.54,1.65) 7(1.27,1.65) 8(0,1.65) 9(-1.27,1.65) 10(-2.54,1.65)
  silkscreen extent -3.3,-2.87 3.3,1.65, body extent -3.4,-2.3 3.4,2.3, height 0.25
FP-GJM155-0_05-IPC_C [mm]
  rect 0.515x0.472 smd paste+0 mask+0: 1(-0.379,0) 2(0.379,0)
  silkscreen extent -0.64,-0.67 0.64,0.67, body extent -0.74,-0.38 0.74,0.38, height 0.25
FP-GQM187-0_15-IPC_B [mm]
  rect 1.007x0.958 smd paste+0 mask+0: 1(-0.726,0) 2(0.726,0)
  silkscreen extent -1.23,-0.88 1.23,0.88, body extent -0.8,-0.4 0.8,0.4, height 0.8
FP-GRM188-0_2-IPC_C [mm]
  rect 0.905x0.906 smd paste+0 mask+0: 1(-0.601,0) 2(0.601,0)
  silkscreen extent -1.05,-0.9 1.05,0.9, body extent -0.8,-0.4 0.8,0.4, height 1
FP-LQFP144-1A-MFG [mm]
  rect 1.35x0.35 smd paste+0 mask+0: 1(-10.625,8.75) 2(-10.625,8.25) 3(-10.625,7.75) 4(-10.625,7.25) 5(-10.625,6.75) 6(-10.625,6.25) 7(-10.625,5.75) 8(-10.625,5.25) 9(-10.625,4.75) 10(-10.625,4.25) 11(-10.625,3.75) 12(-10.625,3.25) 13(-10.625,2.75) 14(-10.625,2.25) 15(-10.625,1.75) 16(-10.625,1.25) 17(-10.625,0.75) 18(-10.625,0.25) 19(-10.625,-0.25) 20(-10.625,-0.75) 21(-10.625,-1.25) 22(-10.625,-1.75) 23(-10.625,-2.25) 24(-10.625,-2.75) 25(-10.625,-3.25) 26(-10.625,-3.75) 27(-10.625,-4.25) 28(-10.625,-4.75) 29(-10.625,-5.25) 30(-10.625,-5.75) 31(-10.625,-6.25) 32(-10.625,-6.75) 33(-10.625,-7.25) 34(-10.625,-7.75) 35(-10.625,-8.25) 36(-10.625,-8.75) 73(10.625,-8.75) 74(10.625,-8.25) 75(10.625,-7.75) 76(10.625,-7.25) 77(10.625,-6.75) 78(10.625,-6.25) 79(10.625,-5.75) 80(10.625,-5.25) 81(10.625,-4.75) 82(10.625,-4.25) 83(10.625,-3.75) 84(10.625,-3.25) 85(10.625,-2.75) 86(10.625,-2.25) 87(10.625,-1.75) 88(10.625,-1.25) 89(10.625,-0.75) 90(10.625,-0.25) 91(10.625,0.25) 92(10.625,0.75) 93(10.625,1.25) 94(10.625,1.75) 95(10.625,2.25) 96(10.625,2.75) 97(10.625,3.25) 98(10.625,3.75) 99(10.625,4.25) 100(10.625,4.75) 101(10.625,5.25) 102(10.625,5.75) 103(10.625,6.25) 104(10.625,6.75) 105(10.625,7.25) 106(10.625,7.75) 107(10.625,8.25) 108(10.625,8.75)
  rect 0.35x1.35 smd paste+0 mask+0: 37(-8.75,-10.625) 38(-8.25,-10.625) 39(-7.75,-10.625) 40(-7.25,-10.625) 41(-6.75,-10.625) 42(-6.25,-10.625) 43(-5.75,-10.625) 44(-5.25,-10.625) 45(-4.75,-10.625) 46(-4.25,-10.625) 47(-3.75,-10.625) 48(-3.25,-10.625) 49(-2.75,-10.625) 50(-2.25,-10.625) 51(-1.75,-10.625) 52(-1.25,-10.625) 53(-0.75,-10.625) 54(-0.25,-10.625) 55(0.25,-10.625) 56(0.75,-10.625) 57(1.25,-10.625) 58(1.75,-10.625) 59(2.25,-10.625) 60(2.75,-10.625) 61(3.25,-10.625) 62(3.75,-10.625) 63(4.25,-10.625) 64(4.75,-10.625) 65(5.25,-10.625) 66(5.75,-10.625) 67(6.25,-10.625) 68(6.75,-10.625) 69(7.25,-10.625) 70(7.75,-10.625) 71(8.25,-10.625) 72(8.75,-10.625) 109(8.75,10.625) 110(8.25,10.625) 111(7.75,10.625) 112(7.25,10.625) 113(6.75,10.625) 114(6.25,10.625) 115(5.75,10.625) 116(5.25,10.625) 117(4.75,10.625) 118(4.25,10.625) 119(3.75,10.625) 120(3.25,10.625) 121(2.75,10.625) 122(2.25,10.625) 123(1.75,10.625) 124(1.25,10.625) 125(0.75,10.625) 126(0.25,10.625) 127(-0.25,10.625) 128(-0.75,10.625) 129(-1.25,10.625) 130(-1.75,10.625) 131(-2.25,10.625) 132(-2.75,10.625) 133(-3.25,10.625) 134(-3.75,10.625) 135(-4.25,10.625) 136(-4.75,10.625) 137(-5.25,10.625) 138(-5.75,10.625) 139(-6.25,10.625) 140(-6.75,10.625) 141(-7.25,10.625) 142(-7.75,10.625) 143(-8.25,10.625) 144(-8.75,10.625)
  silkscreen extent -12.02,-10.1 10.1,10.1, body extent -11.4,-11.4 11.4,11.4, height 0.25
FP-RC0603-0_55-IPC_C [mm]
  rect 0.659x0.812 smd paste+0 mask+0: 1(-0.677,0) 2(0.677,0)
  silkscreen extent -1.01,-0.85 1.01,0.85, body extent -0.8,-0.4 0.8,0.4, height 0.55
FP-RG1608-IPC_C [mm]
  rect 0.855x0.906 smd paste+0 mask+0: 1(-0.626,0) 2(0.626,0)
  silkscreen extent -1.05,-0.9 1.05,0.9, body extent -0.8,-0.4 0.8,0.4, height 0.5
FP-RNP0030A-MFG [mm]
  rrect40% 0.75x0.25 smd paste+0 mask+0: 1(-1.825,2.5) 2(-1.825,2) 3(-1.825,1.5) 4(-1.825,1) 5(-1.825,0.5) 6(-1.825,0) 7(-1.825,-0.5) 8(-1.825,-1) 9(-1.825,-1.5) 10(-1.825,-2) 11(-1.825,-2.5) 16(1.825,-2.5) 17(1.825,-2) 18(1.825,-1.5) 19(1.825,-1) 20(1.825,-0.5) 21(1.825,0) 22(1.825,0.5) 23(1.825,1) 24(1.825,1.5) 25(1.825,2) 26(1.825,2.5)
  rrect40% 0.25x0.6 smd paste+0 mask+0: 12(-0.75,-2.9) 13(-0.25,-2.9) 14(0.25,-2.9) 15(0.75,-2.9) 27(0.75,2.9) 28(0.25,2.9) 29(-0.25,2.9) 30(-0.75,2.9)
  rrect5% 2.2x4.6 smd paste-1000 mask+0: 31(0,0)
  silkscreen extent -2.9,-3.05 2.05,3.05, body extent -2.3,-3.3 2.3,3.3, height 0.25
FP-RP73P-1E-MFG [mm]
  rect 0.5x0.6 smd paste+0 mask+0: 1(-0.5,0) 2(0.5,0)
  silkscreen extent -0.53,-0.77 0.53,0.75, body extent -0.85,-0.4 0.85,0.4, height 0.25
FP-RT0603-IPC_C [mm]
  rect 0.659x0.812 smd paste+0 mask+0: 1(-0.677,0) 2(0.677,0)
  silkscreen extent -1.01,-0.85 1.01,0.85, body extent -0.76,-0.4 0.84,0.4, height 0.58
FP-RT0603-MFG [mm]
  rect 0.9x0.8 smd paste+0 mask+0: 1(-0.85,0) 2(0.85,0)
  silkscreen extent -0.85,-0.81 0.86,0.8, body extent -0.76,-0.4 0.84,0.4, height 0.58
FP-S3B-PH-SM4-TB_LF_SN-MFG [mm]
  rect 1x3.5 smd paste+0 mask+0: 1(-2,-3.25) 2(0,-3.25) 3(2,-3.25)
  rect 1.5x3.4 smd paste+0 mask+0: 4(-4.35,2.3) 5(4.35,2.3)
  silkscreen extent -4.95,-5.75 4.95,3.8, body extent -5.2,-5.1 5.2,4.1, height 0.25
FP-SMBJ-MFG [mm]
  rect 2.16x2.26 smd paste+0 mask+0: 1(-2.45,0) 2(2.45,0)
  silkscreen extent -4.25,-1.97 2.37,1.97, body extent -3.63,-2.07 3.63,2.07, height 0.25
FTSH10701LDVKTR [mm]
  rect 0.74x2.79 smd: 1(-3.81,-2.035) 2(-3.81,2.035) 3(-2.54,-2.035) 4(-2.54,2.035) 5(-1.27,-2.035) 6(-1.27,2.035) 7(0,-2.035) 8(0,2.035) 9(1.27,-2.035) 10(1.27,2.035) 11(2.54,-2.035) 12(2.54,2.035) 13(3.81,-2.035) 14(3.81,2.035)
  silkscreen extent -4.44,-4 4.44,0.4, body extent -4.44,-2.92 4.44,2.92, height 6.12
GCT_USB4940-00-A_REVA [mm]
  rect 0.6x1.15 smd paste+0 mask+0.102: A1_B12(-3.2,1.075) A4_B9(-2.4,1.075) B1_A12(3.2,1.075) B4_A9(2.4,1.075)
  rect 0.3x1.15 smd paste+0 mask+0.102: A5(-1.25,1.075) A6(-0.25,1.075) A7(0.25,1.075) A8(1.25,1.075) B5(1.75,1.075) B6(0.75,1.075) B7(-0.75,1.075) B8(-1.75,1.075)
  rect 2.18x2 smd paste+0 mask+0.102: SH1(-5.11,0.5) SH2(5.11,0.5) SH3(-5.11,-3.43) SH4(5.11,-3.43)
  round 0.65 hole 0.65 unplated mask+0: ""(-2.89,0) ""(2.89,0)
  silkscreen extent -4.47,-6.28 4.47,2.33
"JST- S2B-PH-SM4-TB(LF)(SN)-2_V" [mm] "SMD, 2-Leads, Body 7.9x7.6mm, Pitch 2mm"
  rect 1x3.5 smd: 1(-1,3.45) 2(1,3.45)
  rect 1.5x3.4 smd: MP1(-3.35,-2.3) MP2(3.35,-2.3)
  silkscreen extent -3.95,-3.8 3.95,5.87, body extent -3.95,-3.8 3.95,4.8, height 5.6
RESC1608X50N [mm]
  rect 0.85x1 smd: 1(-0.75,0) 2(0.75,0)
  body extent -0.77,-0.43 0.78,0.42, height 0.45
SBRT10U50SP513 [mm]
  rect 1.39x1.4 smd: 1(-0.92,-2.77) 2(0.92,-2.77)
  rect 3.36x4.86 smd: 3(0,1.212)
  silkscreen extent -2,-3.9 1.98,2.8, body extent -1.98,-3.33 1.98,3.31, height 1.25
SODFL3718X102N [mm]
  rect 1.09x1.11 smd: 1(-1.575,0) 2(1.575,0)
  silkscreen extent -2.12,-0.9 1.38,0.9, body extent -1.85,-0.9 1.85,0.9, height 1.02
SOIC127P600X175-8N [mm]
  rect 1.525x0.65 smd: 1(-2.712,1.905) 2(-2.712,0.635) 3(-2.712,-0.635) 4(-2.712,-1.905) 5(2.712,-1.905) 6(2.712,-0.635) 7(2.712,0.635) 8(2.712,1.905)
  silkscreen extent -3.47,-2.45 1.6,2.58, body extent -3,-2.45 3,2.45, height 1.75
SON127P800X600X80-9N-D [mm]
  rect 0.95x0.45 smd: 1(-3.9,1.905) 2(-3.9,0.635) 3(-3.9,-0.635) 4(-3.9,-1.905) 5(3.9,-1.905) 6(3.9,-0.635) 7(3.9,0.635) 8(3.9,1.905)
  rect 3.45x4.35 smd: 9(0,0)
  silkscreen extent -4.5,2.51 -4.25,2.76, body extent -4.05,-3 4.05,3, height 0.8
SOT95P280X145-6N [mm]
  rect 1.2x0.6 smd: 1(-1.25,0.95) 2(-1.25,0) 3(-1.25,-0.95) 4(1.25,-0.95) 5(1.25,0) 6(1.25,0.95)
  silkscreen extent -1.85,-1.46 0.3,1.6, body extent -1.4,-1.46 1.4,1.46, height 1.45
WL-SMCD_0603 [mm] "SMD Mono-color Chip LED, body 1.6x0.8mm"
  rect 0.8x0.75 smd: 1(-1270.8,-1270) 2(-1269.2,-1270)
  silkscreen extent -1271.62,-1270.4 -1269.78,-1269.6, body extent -1270.8,-1270.4 -1269.2,-1269.6, height 0.42
WL-SMCW_0603_150060xx75000 [mm] "SMD Mono-color Chip LED, body 1.6x0.8mm"
  rect 0.8x0.8 smd: 1(-0.8,0) 2(0.8,0)
  silkscreen extent -1.55,-0.4 -1.4,0.4, body extent -0.8,-0.4 0.8,0.4, height 0.7
WL-SMCW_0603_150060xx75020 [mm] "SMD Mono-color Chip LED, body 1.6x0.8mm"
  rect 0.8x0.8 smd: 1(-0.8,0) 2(0.8,0)
  silkscreen extent -1.62,-0.08 -1.48,0.07, body extent -0.8,-0.4 0.8,0.4, height 0.25

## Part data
C1 C2 C16 C20 C24 C26 C27 C28 C29 C30 C31 C32 C33 C34 C35 C36 C38 C47 C71: library part CMP-13271-002683-1, "Cap Ceramic 100nF 16V X7R ±10% Pad SMD 0603 +125°C T/R / CL10B104KO8WPNC", Capacitance=100nF, Case Code (Imperial)=0603, Case Code (Metric)=1608, Max Operating Temperature=125°C, Min Operating Temperature=-55°C, Ratings=AEC-Q200, Tolerance=10%, Voltage Rating=16V
C3 C4: library part CMP-06035-061124-1, "GQM1875C2E4R0BB12D / Ceramic Capacitor 4pF ±0.1pF 250VDC C0G 0603 Paper T/R", Case Code (Imperial)=0603, Case Code (Metric)=1608, Dielectric=C0G, Max Operating Temperature=125°C, Min Operating Temperature=-55°C, Package Quantity=4000, Voltage Rating=250V
C5 C6: library part CMP-03020-023157-1, "C0603 1.5 pF X8R 30ppm/°C 0.1 pF 25 V / C0603C159B3HACTU", Capacitance="1.5 pF", Manufacturer=KEMET, Manufacturer Part Number=C0603C159B3HACTU, Package=C0603C-CF, Temperature="-55°C to +125°C", Temperature Characteristic=X8R, Temperature Coefficient=30ppm/°C, Temperature Range High=+125°C, Temperature Range Low=-55°C, Tolerance="0.1 pF", Voltage Rating="25 V"
C7: library part CMP-2008-03910-2, "Multi-Layer Ceramic Capacitor 0.75pF C0G  ±0.1pF 0402 Paper T/R", Capacitance=0.75pF, Case Code (Imperial)=0402, Case Code (Metric)=1005, Dielectric=C0G, Max Operating Temperature=125°C, Min Operating Temperature=-55°C, Package Quantity=1, Voltage Rating=50V
C8: library part CMP-001-00127-1, "Cap Ceramic 0.1uF 25V X7R 5% SMD 0805 FlexiTerm 125°C Paper T/R", Case/Package=0805, Max Operating Temperature=125°C, Min Operating Temperature=-55°C, Tolerance=5%, Voltage Rating=25V
C11 C13 C14: library part CMP-06035-043613-1, "GRM188R61H225ME11J Chip Multilayer Ceramic Capacitors for General Purpose, 0603, 2.2uF, X5R, 15%, 20%, 50V"
C12 C15 C18: library part CMP-14477-000175-2, "UMK107ABJ474KA-T", Capacitance=470nF, Case Code (Imperial)=0603, Case Code (Metric)=1608, Dielectric=X5R, Max Operating Temperature=85°C, Min Operating Temperature=-55°C, Package Quantity=1, Tolerance=10%, Voltage=50V
C19 C37 C39: library part CMP-13271-003287-1, "Cap Ceramic 10uF 16V X6S ±20% Pad SMD 0603 +105°C T/R / CL10X106MO8NRNC", Case Code (Imperial)=0603, Case Code (Metric)=1608, Max Operating Temperature=105°C, Min Operating Temperature=-55°C, Tolerance=20%, Voltage Rating=16V
C21 C22: library part CMP-13271-003360-1, "Cap Ceramic 2.2uF 16V X5R ±10% Pad SMD 0603 +85°C T/R / CL10A225KO8NNND", Capacitance=2.2nF, Case/Package=0603, Dielectric=X5R, Max Operating Temperature=85°C, Min Operating Temperature=-55°C, Tolerance=10%, Voltage Rating (DC)=16V
C23 C46 C46_CANTransceiver2 C48: library part CMP-13271-000784-1, "Cap Ceramic 1uF 16V X7R ±10% Pad SMD 0603 +125°C T/R / CL10B105KO8NNNL", Case/Package=0603, Dielectric=X7R, Max Operating Temperature=125°C, Min Operating Temperature=-55°C, Package Quantity=15000, Tolerance=10%, Voltage Rating=16V
C25: library part CMP-08246-005518-1, "Multilayer Ceramic Capacitors 4.7μF ±10% 25V X5R SMD 0603 / C1608X5R1E475K080AC", Case Code (Imperial)=0603, Case Code (Metric)=1608, Dielectric=X5R, Dielectric Material=Ceramic, Max Operating Temperature=85°C, Min Operating Temperature=-55°C, Package Quantity=4000, Tolerance=10%, Voltage Rating=25V
D1: library part CMP-1426-00001-3, Case Code (Imperial)=0603, Case Code (Metric)=1608, Color=Red, Forward Current=100mA, Forward Voltage=2V, Max Junction Temperature (Tj)=95°C, Max Operating Temperature=85°C, Max Reverse Voltage (DC)=5V, Min Operating Temperature=-40°C, Power Dissipation=72mW, Test Current=20mA
D2: library part CMP-03913-90235563-2, "150060GS55040 WL-SMCD SMT Mono-color Chip LED Diffused", Forward Current=60mA, Forward Voltage=3.2V, Max Operating Temperature=85°C, Max Reverse Voltage (DC)=5V, Min Operating Temperature=-40°C
D3: library part CMP-03913-104891429-2, "WL-SMCW SMT Mono-Color Chip LED Waterclear super f", Forward Current=60mA, Forward Voltage=2V, Max Operating Temperature=85°C, Max Reverse Voltage (DC)=5V, Min Operating Temperature=-40°C
D4: library part CMP-90577-000001-1, "Schottky Diodes & Rectifiers SOT23CA.0.2A 30V Sch ottky", Capacitance=10pF, Case/Package=SOT-23, Current Rating=200mA, Forward Voltage=1V, Voltage Rating (DC)=30V
D5: library part CMP-2000-07095-2, "TVS DIODE 33V 53.3V DO214AA", Breakdown Voltage=36.7V, Clamping Voltage=53.3V, Manufacturer="Littelfuse Inc", Max Junction Temp=+150°C, Package=SMBJ, Peak Pulse Current=11.3A, Peak Pulse Power=600W, Reverse Standoff Voltage=33V, Temperature="-65°C to +150°C", Temperature Range Low=-65°C
D6: "Diode", Manufacturer_Name="Diodes Incorporated", Mouser Part Number=621-SBRT10U50SP5-13
D7: "Diode", Manufacturer_Name="Taiwan Semiconductor", Mouser Part Number=821-SS34LWHRVG
FB1: "Ferrite Bead", Manufacturer_Name=TDK, Mouser Part Number=810-MPZ2012S101AT000
IC1 IC2: "Integrated Circuit", Manufacturer_Name="Texas Instruments", Mouser Part Number=595-TCAN3414DR
IC2: "Integrated Circuit", Manufacturer_Name=Winbond, Manufacturer_Part_Number="W25Q01JVZEIM TU", Mouser Part Number=454-W25Q01JVZEIMTU
IC3: "Integrated Circuit", Manufacturer_Name=STMicroelectronics, Mouser Part Number=511-USBLC6-2SC6
J1: "Connector", Manufacturer_Name=SAMTEC, Mouser Part Number=200-FTSH10701LDVKTR
J2: library part CMP-00257-07672643-1, "43650-0205 Conn Wire to Board HDR 2 POS 3mm Solder RA Side Entry Thru-Hole Micro-Fit 3.0™ Tray", Current Rating=5A, Manufacturer Lifecycle Status=ACTIVE, Voltage Rating=600V
J3: library part CMP-002-00134-1, "Type C USB 2.0 Connector", Case/Package=None
J5: library part CMP-11597-000003-1, "CONN MICRO SD CARD HINGED TYPE", Contact Resistance=100mR, Current Rating=500mA, Flammability Rating="UL94 V-0", Insulation Resistance=1GR, Max Operating Temperature=85°C, Min Operating Temperature=-25°C, Package Quantity=1, Voltage Rating (AC)=125V
J7_CANTransceiver J7_CANTransceiver2 J8_CANTransceiver J8_CANTransceiver2: library part CMP-002-00113-1, "Connector Header, PH Series, 3 Position, Side Entry, 2.00mm, Solder, Surface Mount, Natural.", Max Current Rating=2A, Max Operating Temperature=85°C, Min Operating Temperature=-25°C, Voltage Rating=100V
L2: library part CMP-2000-05082-1, "Shielded Power Inductor, 10 uH, +/- 20%, 10 A, -55 to 125 degC, 2-Pin SMD, RoHS, Tape and Reel", Current - Saturation=16A, Current Rating=10A, DC Resistance (DCR)=16.8mOhmMax, Frequency - Self Resonant=10MHz, Frequency - Test=100kHz, Inductance=10µH, Manufacturer=Bourns, Operating Temperature=-55degC~125degC, Package / Case=Nonstandard, Standard Package=400, Tolerance=±20%
P1: library part CMP-002-00031-2, "Male Header, Pitch 2 mm, 1 x 2 Position, Height 5.5 mm, -25 to 85 degC, RoHS, Tape and Reel", Case/Package=S2B-PH-SM4-TB(LF)(SN)-2, Manufacturer=JST, Max Operating Temperature=85°C, Min Operating Temperature=-25°C, Package Description="Male Header, Pitch 2 mm, 1 x 2 Position, Height 5.5 mm"
R1 R2 R3 R14 R14_CANTransceiver2 R15 R15_CANTransceiver2: library part CMP-03412-005349-1, "RES SMD 10K OHM 1% 1/10W 0603 / RT0603FRE0710KL", Manufacturer=Yageo, Manufacturer Part Number=RT0603FRE0710KL, Package=RT0603, Power Rating=0.1W, Resistance=10KΩ, Temperature="-55°C to +155°C", Temperature Coefficient="50 ppm/°C", Temperature Range High=+155°C, Temperature Range Low=-55°C, Tolerance=0.01, Voltage Rating=75V
R4 R5 R6: library part CMP-03412-038529-1, "AF0603JR-07220RL Anti-Sulfurated Chip Resistors Automotive Grade 220Ω 5% 100ppm/°C 0603", Case/Package=0603, Max Operating Temperature=155°C, Max Power Dissipation=100mW, Min Operating Temperature=-55°C, Resistance=220R, Resistor Type="Thick Film", Temperature Coefficient=100ppm/°C, Tolerance=5%
R7: library part CMP-03412-030646-1, "RT0603 100Ω 0.1W 50 ppm/°C 1.00% RT0603FRE07100RL", Manufacturer=Yageo, Manufacturer Part Number=RT0603FRE10100RL, Package=RT0603, Power Rating=0.1W, Resistance=100Ω, Temperature="-55°C to +155°C", Temperature Coefficient="50 ppm/°C", Temperature Range High=+155°C, Temperature Range Low=-55°C, Tolerance=0.01, Voltage Rating=75V
R8 R17: library part CMP-03211-011177-1, "RP73P 0402 165Ω 0.1W 25ppm/°C 0.10% 50V", Manufacturer="TE Connectivity", Manufacturer Part Number=RP73PF1E165RBTD, Package=RP73P-1E, Power Rating=0.1W, Resistance=165Ω, Temperature="-55°C to +155°C", Temperature Coefficient=25ppm/°C, Temperature Range High=+155°C, Temperature Range Low=-55°C, Tolerance=0.10%, Voltage Rating=50V
R9 R10: library part CMP-2100-03662-2, "RC0603FR-07100KL RES SMD 100K OHM 1% 1/10W 0603", Case Code (Imperial)=0603, Case Code (Metric)=1608, Max Operating Temperature=155°C, Max Power Dissipation=100mW, Min Operating Temperature=-55°C, Resistance=100kR, Resistance Tolerance=1%, Resistor Type="Thick Film", Temperature Coefficient=100ppm/°C, Voltage Rating=50V, Working Voltage=75V
R11: library part CMP-2000-02140-2, "RG1608P-2492-B-T5 / Automotive Metal Thin Film Chip Resistor, 0603, 24.9kΩ, 0.1%, 25ppm/°C, 0.1W, 100V", Case Code (Imperial)=0603, Case Code (Metric)=1608, Max Operating Temperature=155°C, Max Power Dissipation=100mW, Min Operating Temperature=-55°C, Package Quantity=1, Resistance=24.9kR, Resistor Type="Thin Film", Temperature Coefficient=25ppm/°C, Tolerance=0.1%, Voltage Rating=100V, Voltage Rating (DC)=75V
R12: library part CMP-03412-029582-1, "RT0603BRD07147KL / RES SMD 147K OHM 0.1% 1/10W 0603", Manufacturer=Yageo, Manufacturer Part Number=RT0603BRD07147KL, Package=RT0603, Power Rating=0.1W, Resistance=147KΩ, Temperature="-55°C to +155°C", Temperature Coefficient="25 ppm/°C", Temperature Range High=+155°C, Temperature Range Low=-55°C, Tolerance=0.001, Voltage Rating=75V
R13: library part CMP-05422-000107-1, "ERJ-PB3B1002V / RES SMD 10K OHM 0.1% 1/5W 0603", Case Code (Imperial)=0603, Case Code (Metric)=1608, Max Operating Temperature=155°C, Max Power Dissipation=200mW, Min Operating Temperature=-55°C, Resistance=10kR, Resistor Type="Thick Film", Temperature Coefficient=50ppm/°C, Tolerance=0.1%
R16 R16_CANTransceiver2: library part CMP-03412-039700-1, "Anti-Sulfurated Chip Resistors Automotive Grade 120Ω 1% 100ppm/°C 0603 AF0603FR-07120RL", Case/Package=0603, Max Operating Temperature=155°C, Max Power Dissipation=100mW, Min Operating Temperature=-55°C, Resistance=120R, Resistor Type="Thick Film", Temperature Coefficient=100ppm/°C, Tolerance=1%
R18 R19: library part CRCW060356K0JNEA, "Resistor / CRCW060356K0JNEA", Manufacturer_Name=Vishay, Mouser Part Number=71-CRCW060356K0JNEA
RN1: library part CMP-00287-42270834-1, "EXB-A10P103J Res Thick Film NET 10K Ohm 5% ±200ppm/℃ BUS Molded 10-Pin 2512 Concave SMD Embossed Carrier T/R", Case Code (Imperial)=2512, Case Code (Metric)=6432, Max Operating Temperature=125°C, Min Operating Temperature=-55°C, Number of Resistors=8, Power Dissipation=63mW, Power Per Element=62.5mW, Resistance=10kΩ, Temperature Coefficient=200ppm/°C, Tolerance=5%, Voltage Rating=50V, Voltage Rating (DC)=100V
U1: library part CMP-12105-000009-1, "LQFP 144 20X20X1.4 2", Ambient Temperature Range High=+85°C, Ambient Temperature Range Low=-40°C, Frequency=480MHz, Manufacturer=STMicroelectronics, Max Junction Temp=+125°C, Max Supply Voltage=3.6V, Min Supply Voltage=1.62V, Package=LQFP144-1A, Temperature="-40°C to +125°C"
U2: library part CMP-04918-000213-1, "3.5-V TO 60-V, 5-A SYNCHRONOUS S"
U3: library part CMP-12153-000011-1, "IC REG LINEAR 3.3V 2A 6DFN", Case/Package=DFN, Dropout Voltage=130mV, Max Input Voltage=6V, Max Operating Temperature=125°C, Min Input Voltage=1.25V, Min Operating Temperature=-40°C, Operating Supply Current=1mA, Output Current=2A, Output Voltage=3.3V, Package Quantity=3000
Y1: library part CMP-27762-007472-1, "Crystal 50MHz ±10ppm 4pF SMD-4 2.5mm x 2mm", Case/Package=SMD/SMT, ESR (Equivalent Series Resistance)=70R, Frequency=50MHz, Frequency Stability=10ppm, Load Capacitance=4pF, Max Operating Temperature=70°C, Min Operating Temperature=-20°C
Y2: library part CMP-27762-015953-1, "Crystal 32.768kHz ±20ppm (Tol) 6pF FUND 70kΩ Automotive 2-Pin Mini-CSMD T/R", Case/Package=SMD/SMT, ESR (Equivalent Series Resistance)=70kR, Frequency=32.768kHz, Frequency Tolerance=20ppm, Load Capacitance=6pF, Max Operating Temperature=85°C, Min Operating Temperature=-40°C, Ratings=AEC-Q200

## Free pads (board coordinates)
  round 5.08 hole 3.2: 2(3.636,3.679) 2(3.636,95.246) 2(95.428,3.63) 2(95.435,95.238)

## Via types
v1: diameter 0.61, hole 0.305, Top Layer 1 to Bottom Layer 1, tented both sides, 441 vias
v2: diameter 0.5, hole 0.2, Top Layer 1 to Bottom Layer 1, 11 vias
v3: diameter 1.27, hole 0.711, Top Layer 1 to Bottom Layer 1, tented both sides, 8 vias
v4: diameter 0.61, hole 0.33, Top Layer 1 to Bottom Layer 1, tented both sides, 1 vias
v5: diameter 0.65, hole 0.305, Top Layer 1 to Bottom Layer 1, tented both sides, 1 vias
